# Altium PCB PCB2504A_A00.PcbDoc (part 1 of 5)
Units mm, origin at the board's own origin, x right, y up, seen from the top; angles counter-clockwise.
Board outline 115 x 60 mm, 6 copper layers (Top Layer, Signal Layer 2, Signal Layer 3, Signal Layer 4, Signal Layer 5, Bottom Layer), stack 1.555 mm thick; 403 components, 294 nets, 1344 pads, 774 vias.
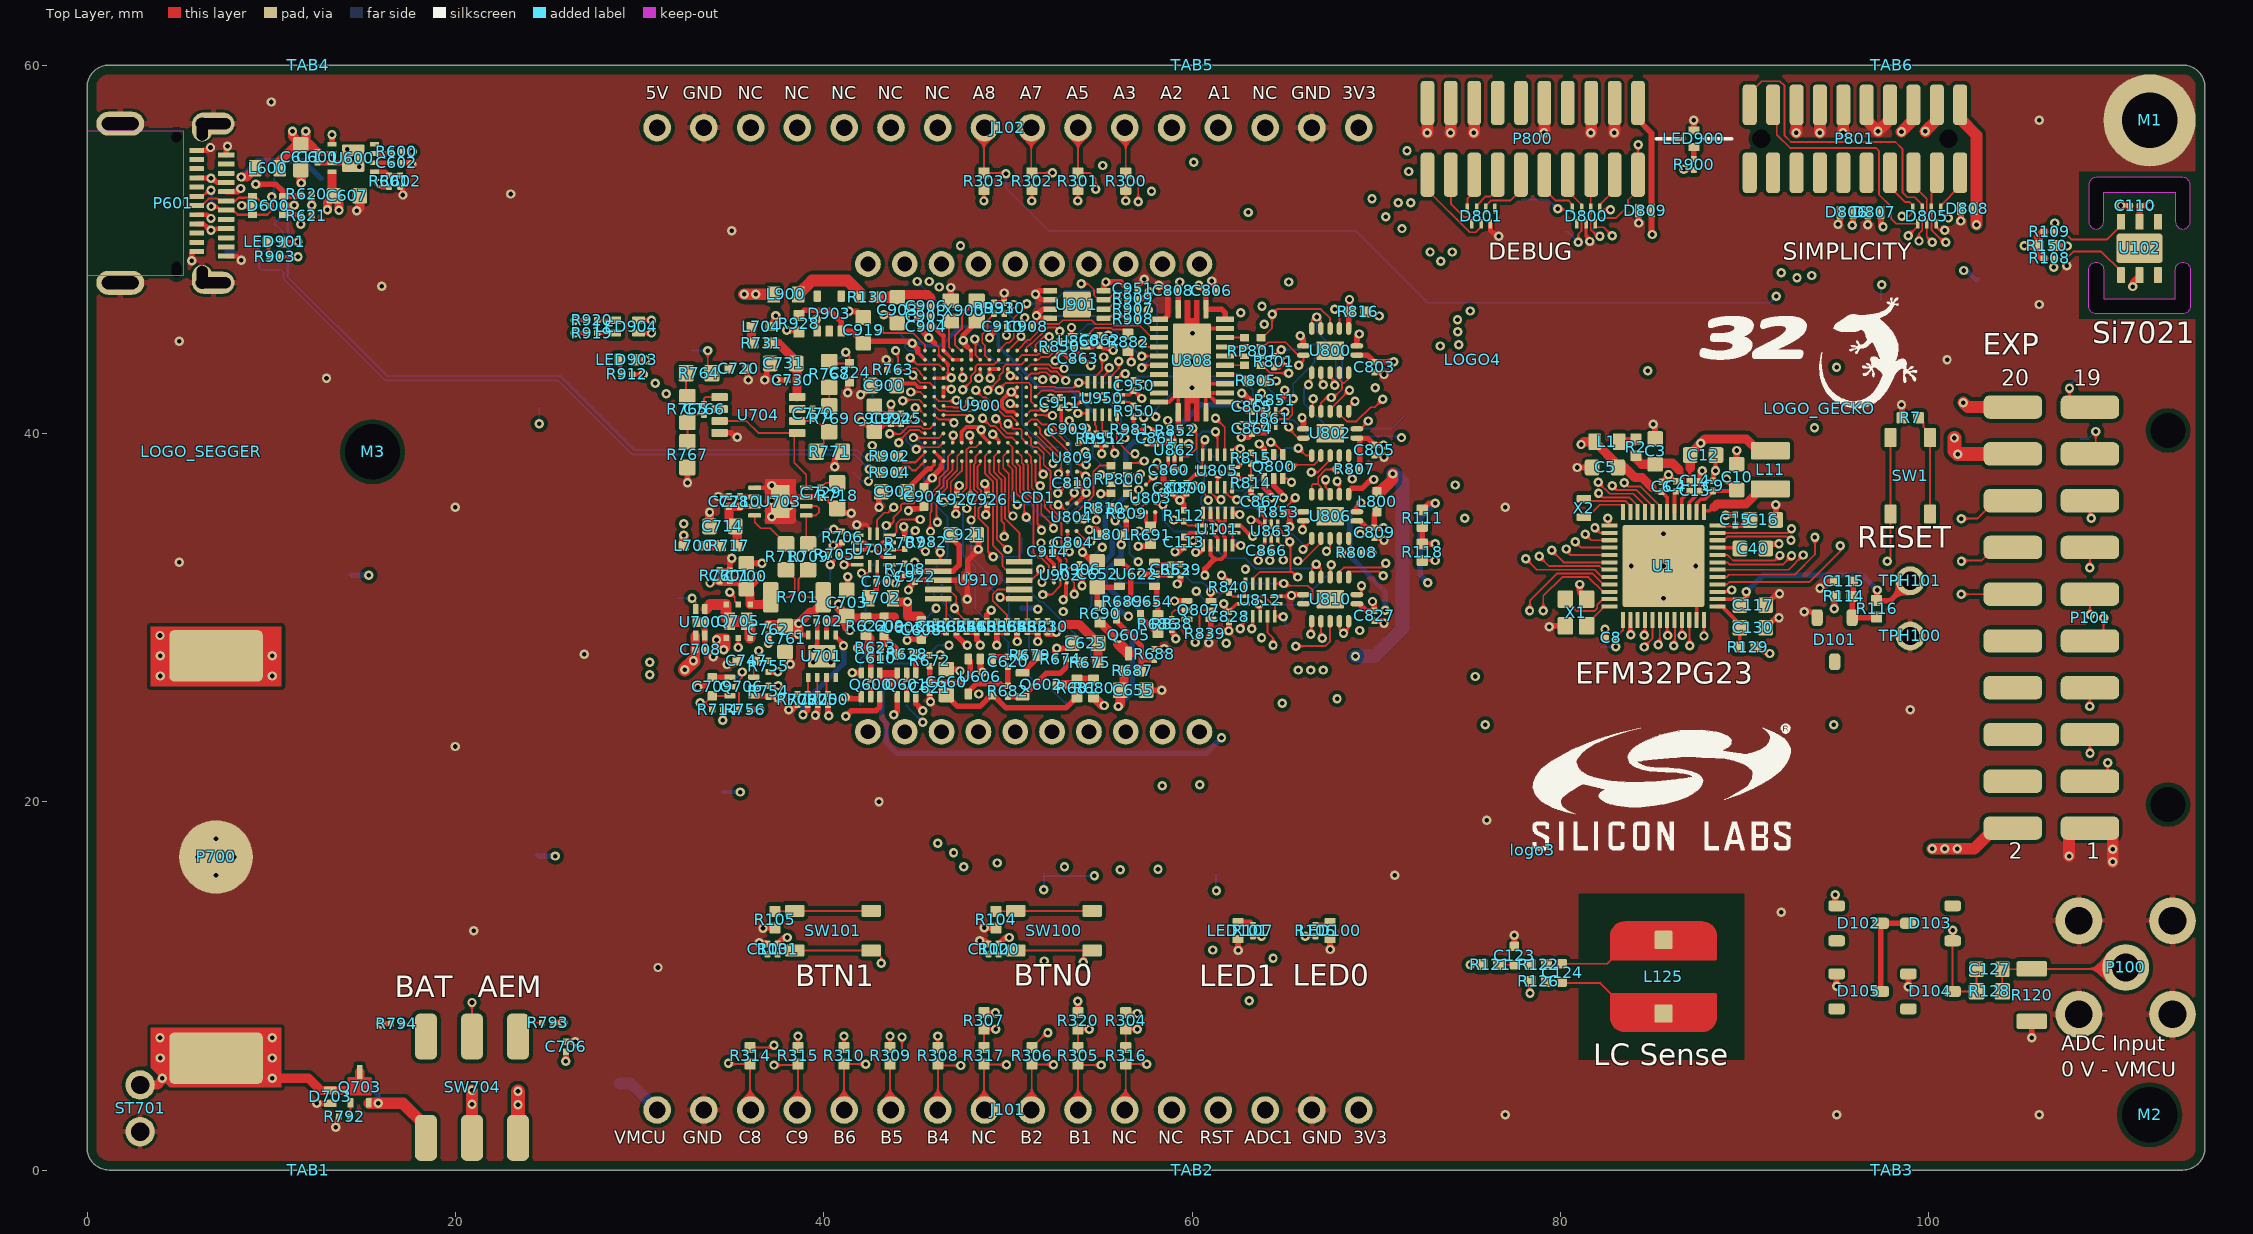
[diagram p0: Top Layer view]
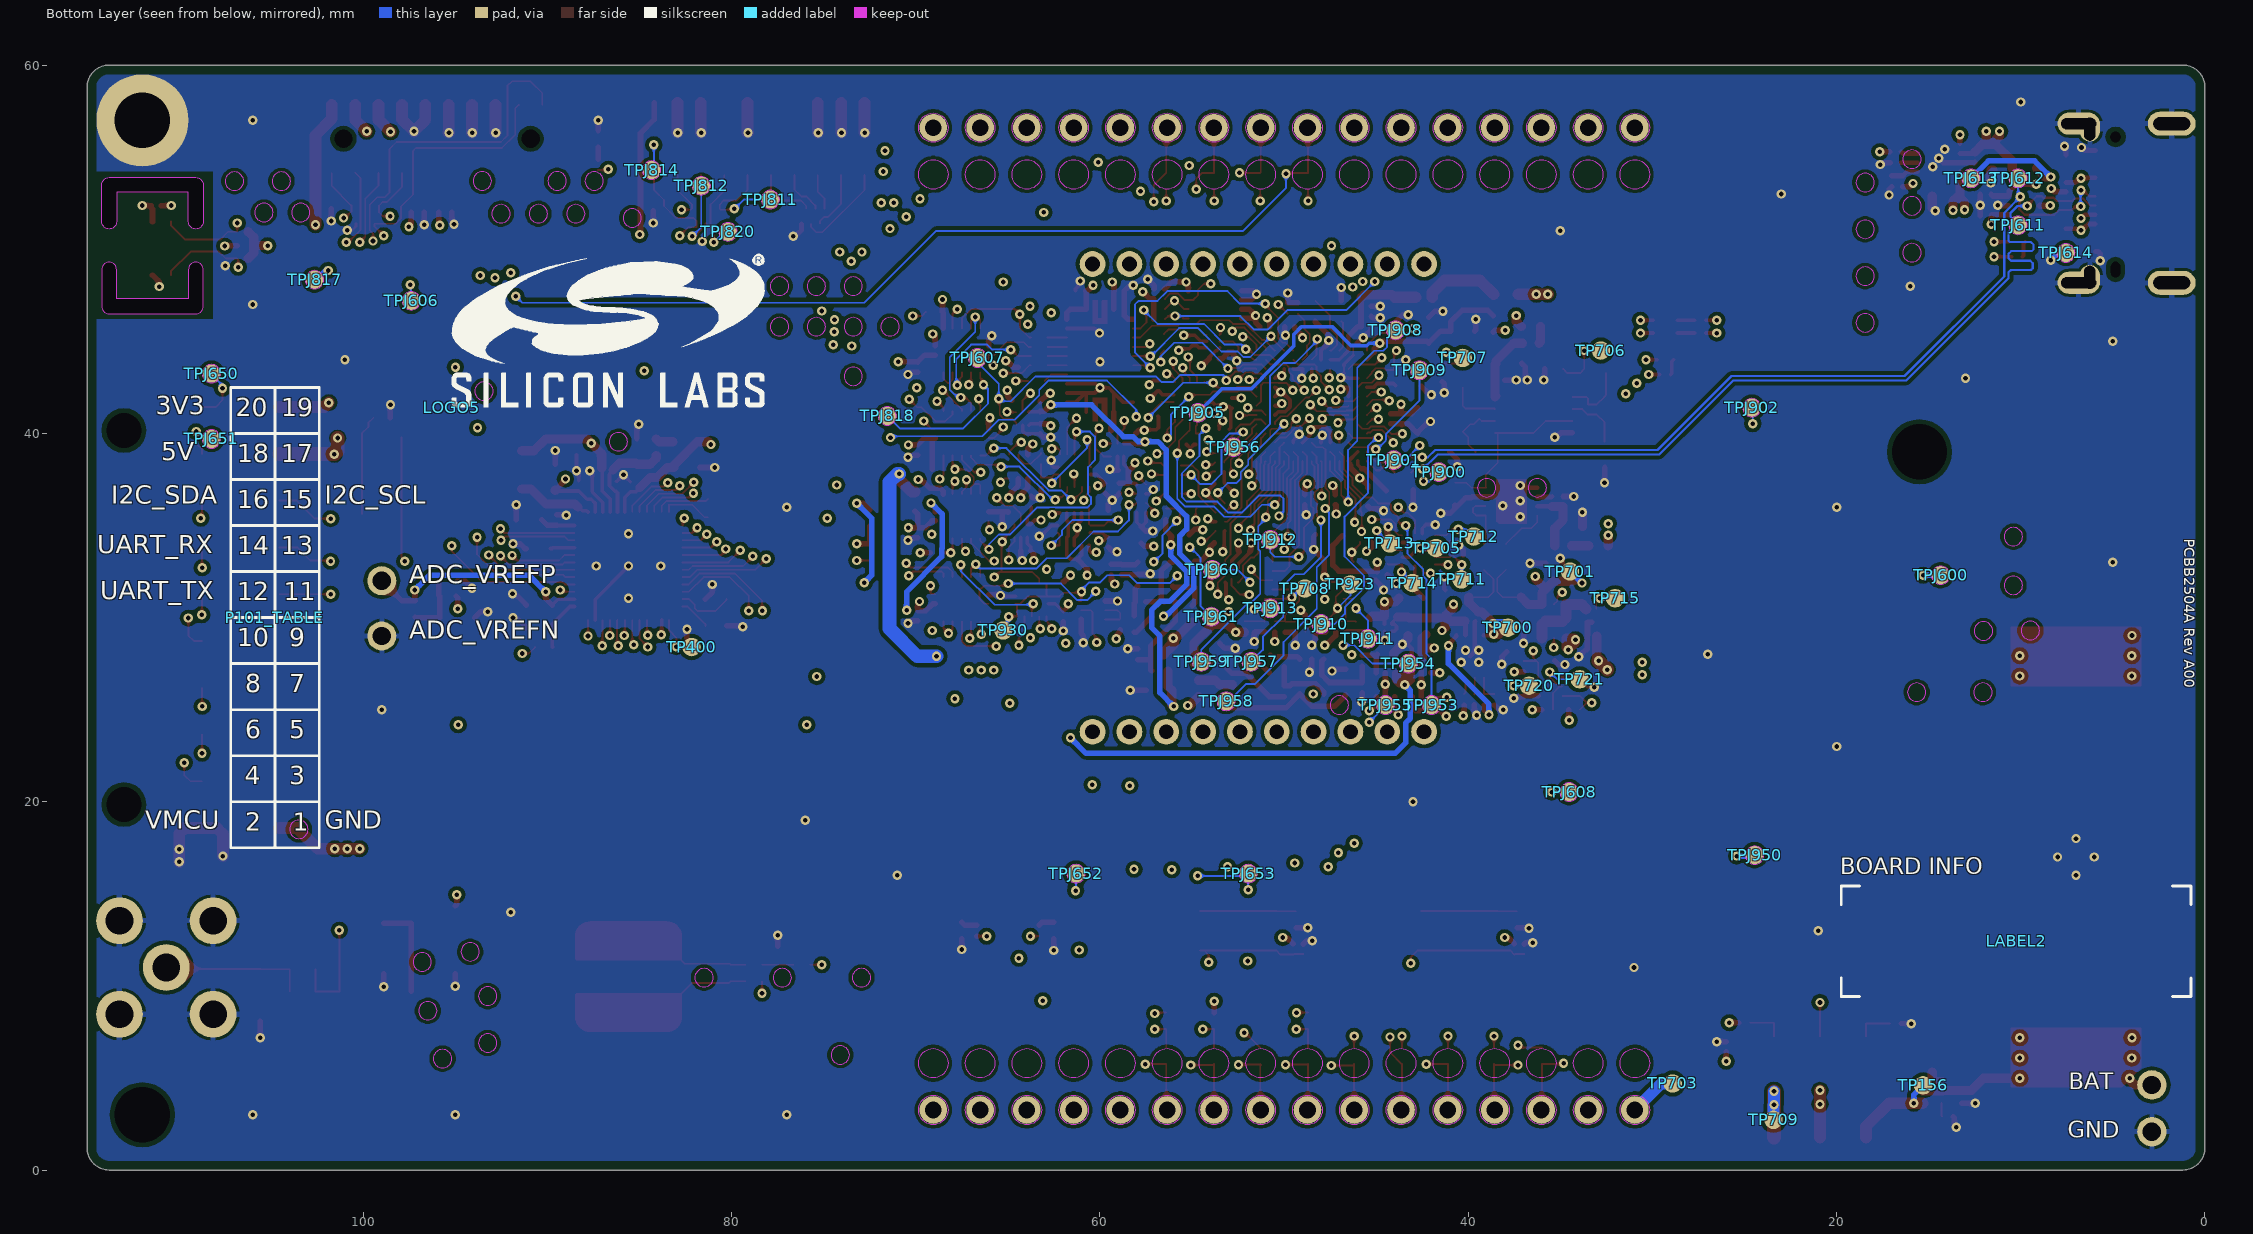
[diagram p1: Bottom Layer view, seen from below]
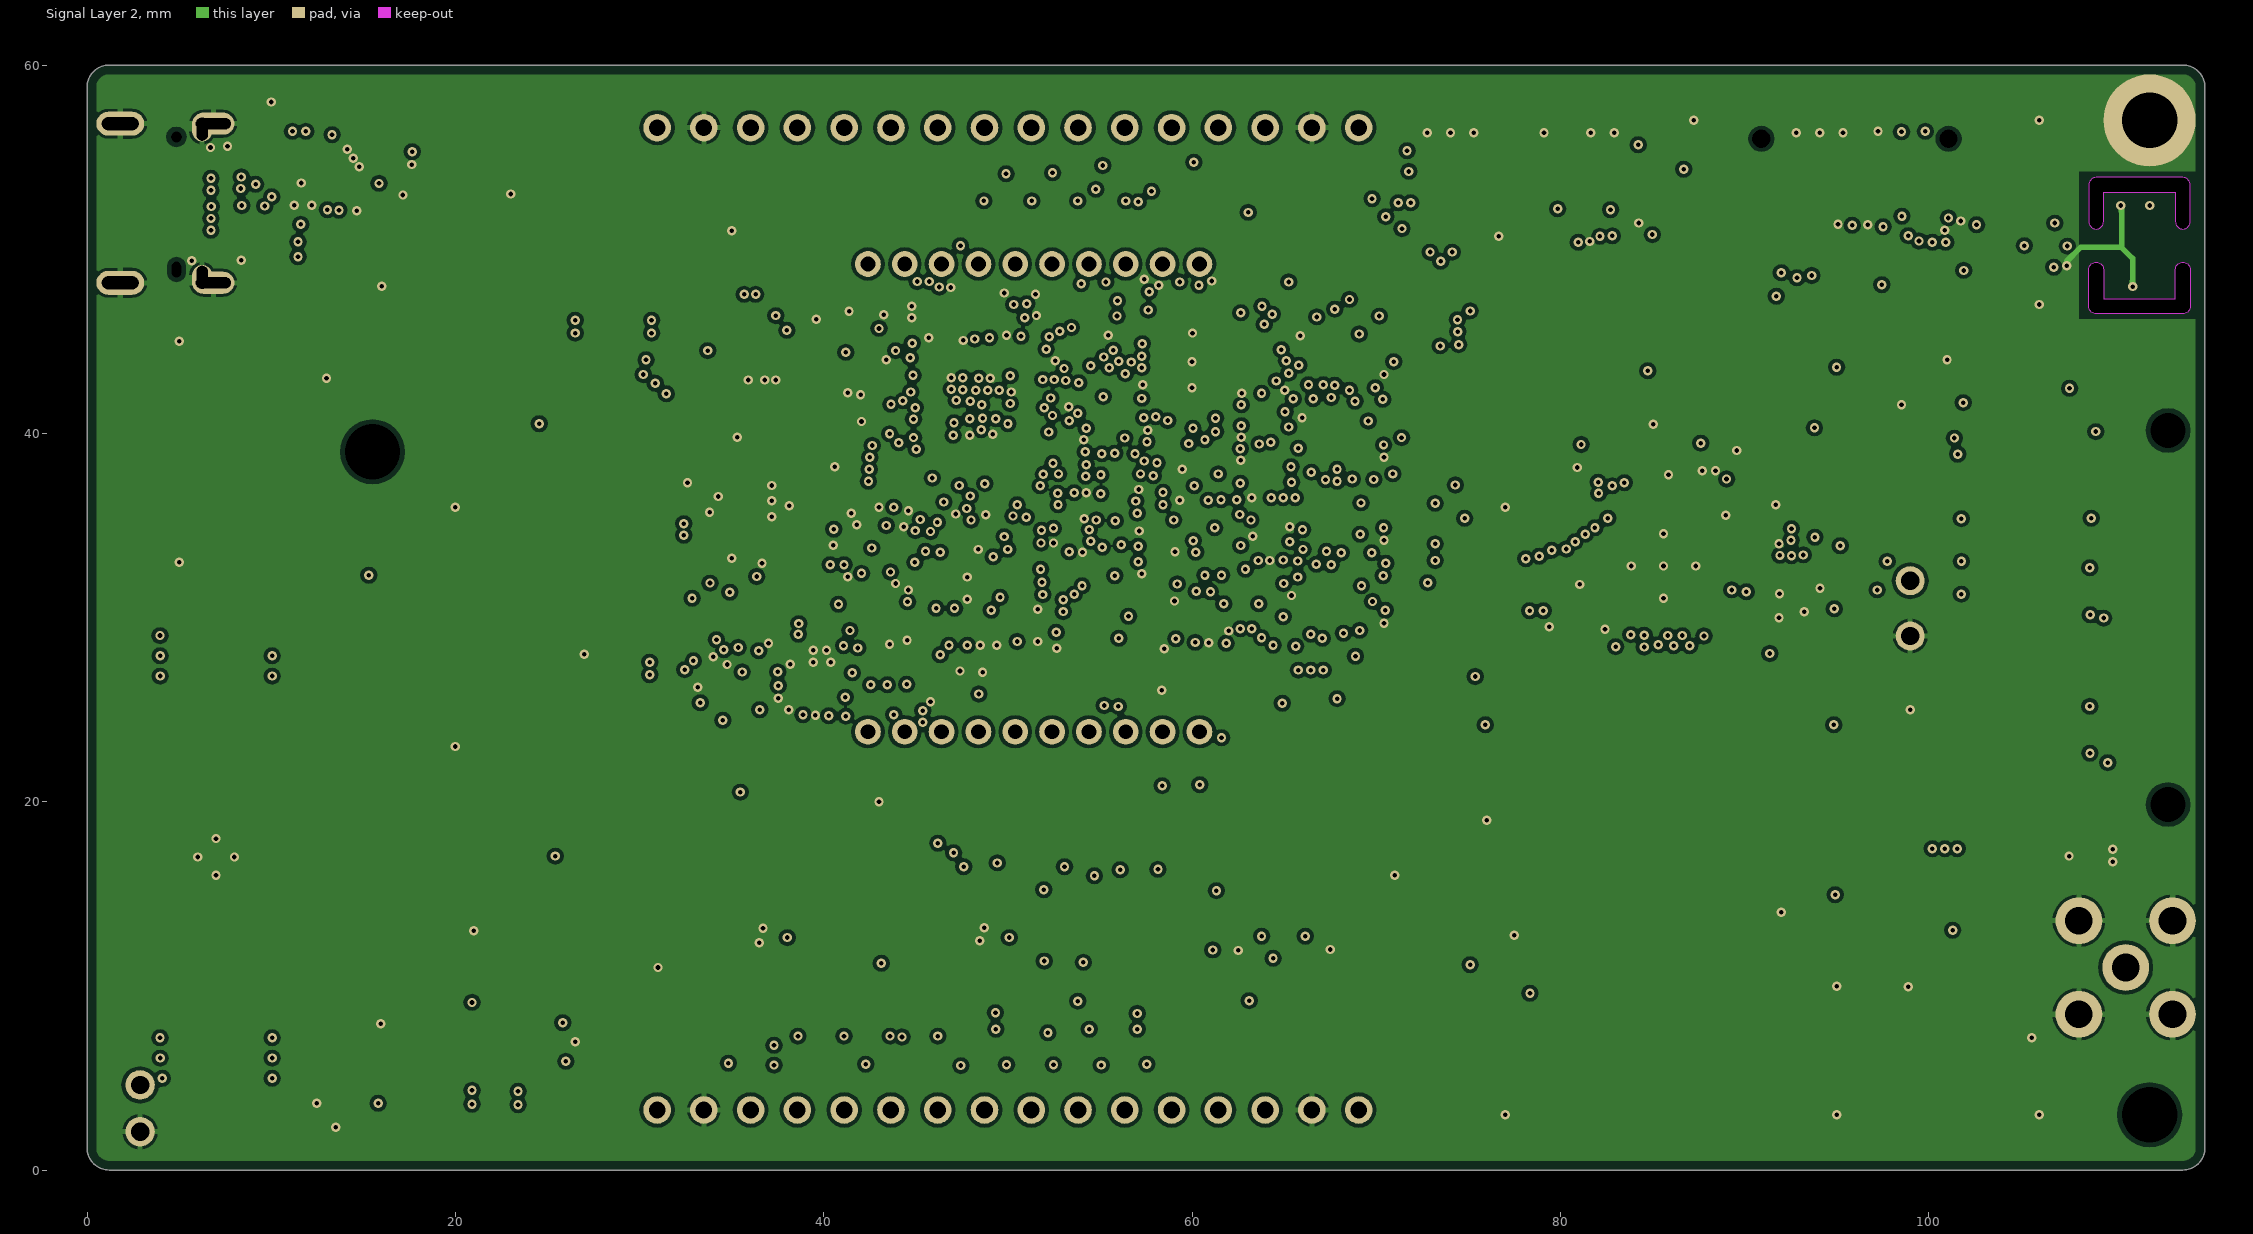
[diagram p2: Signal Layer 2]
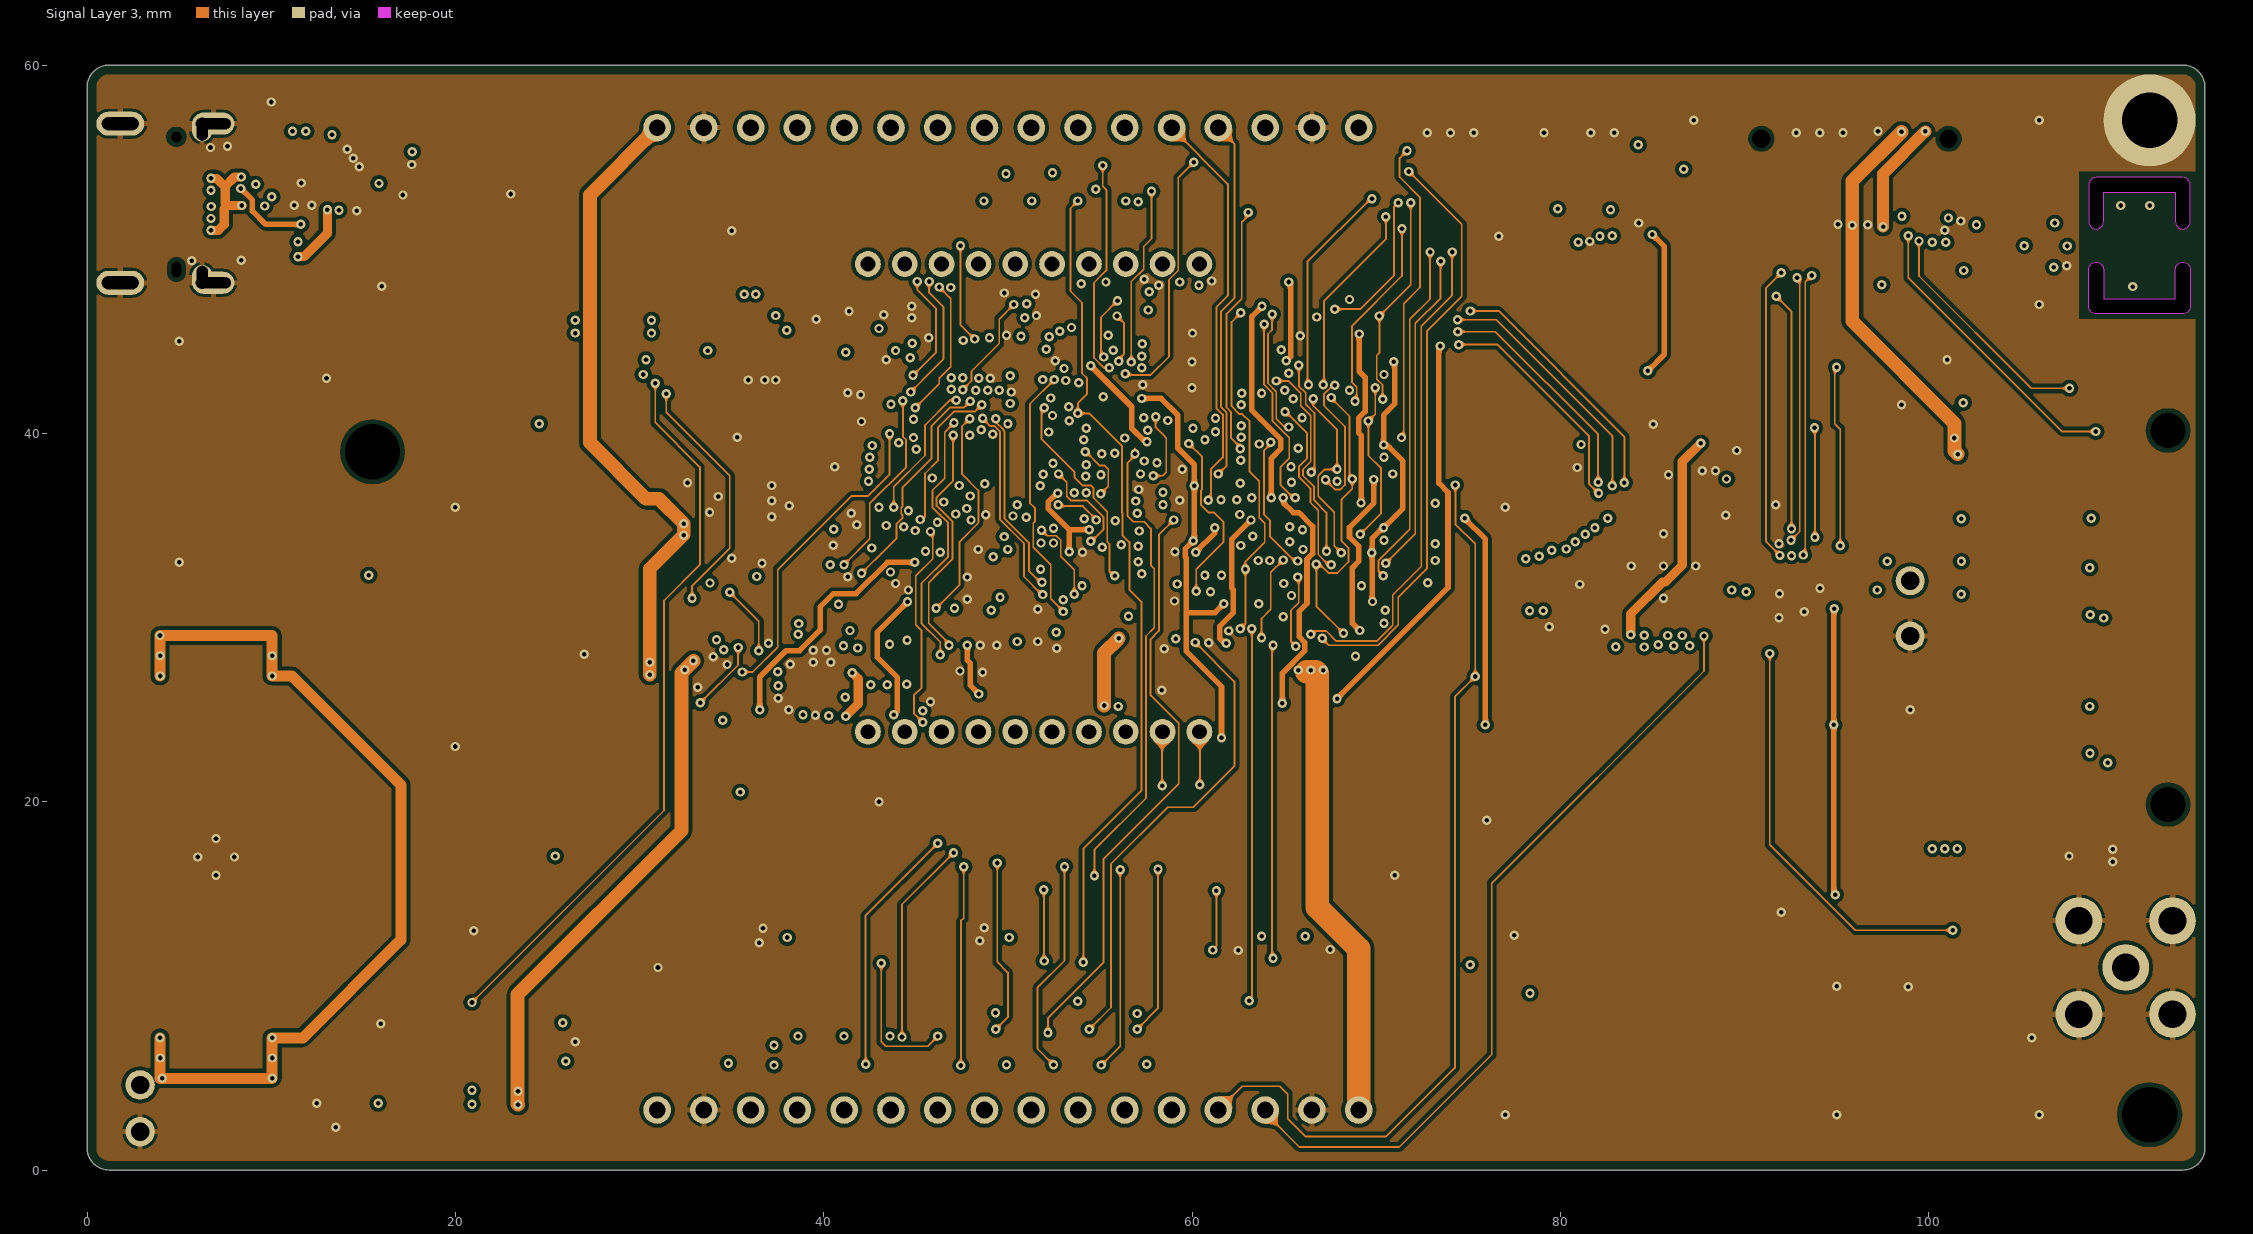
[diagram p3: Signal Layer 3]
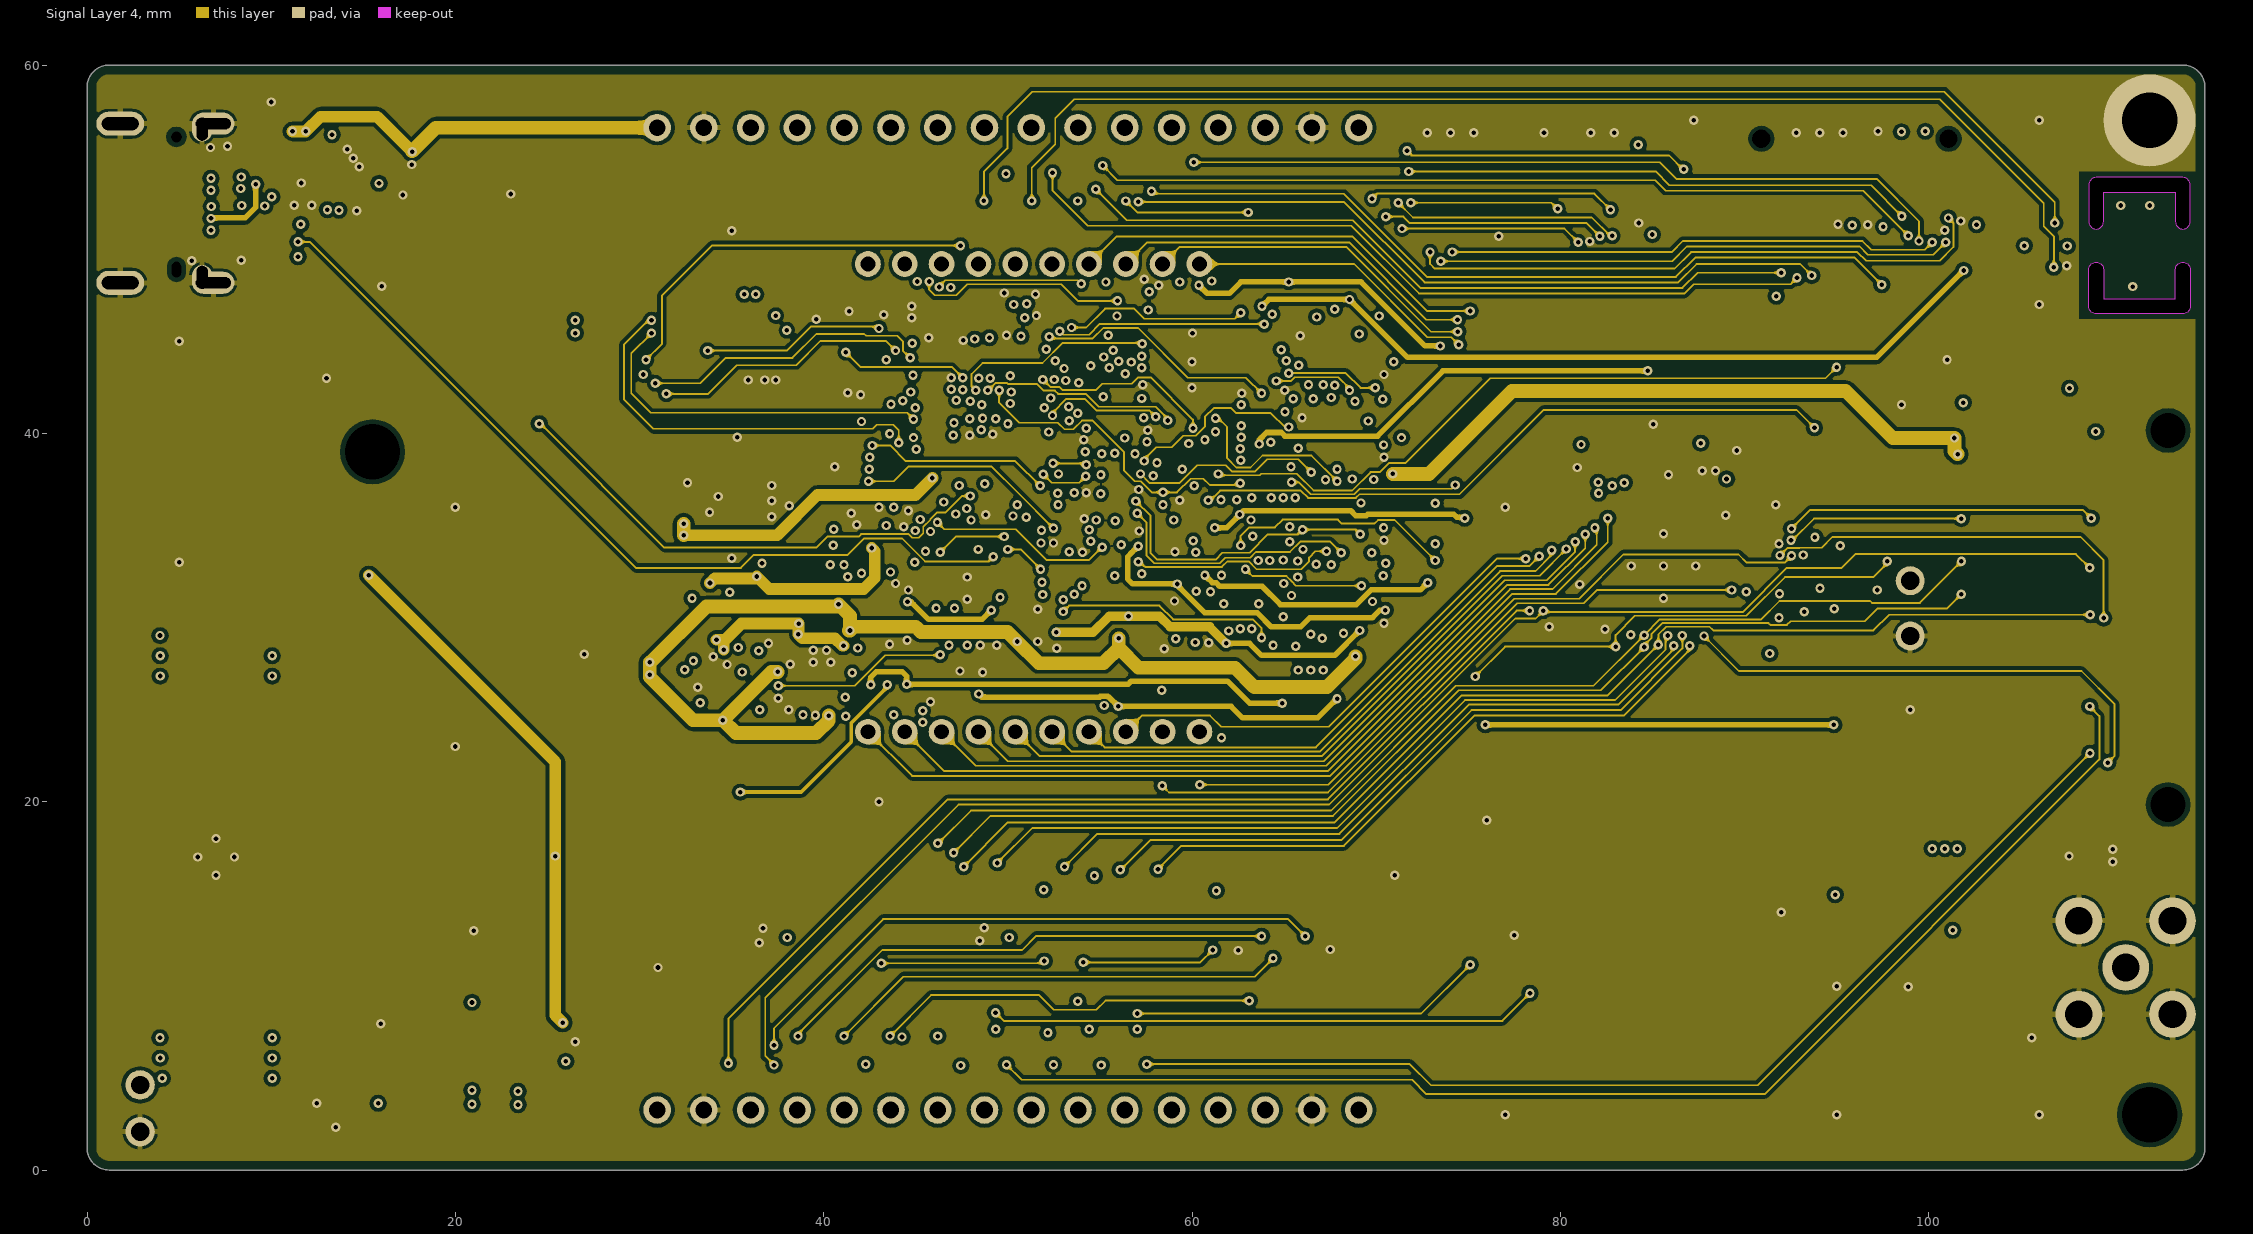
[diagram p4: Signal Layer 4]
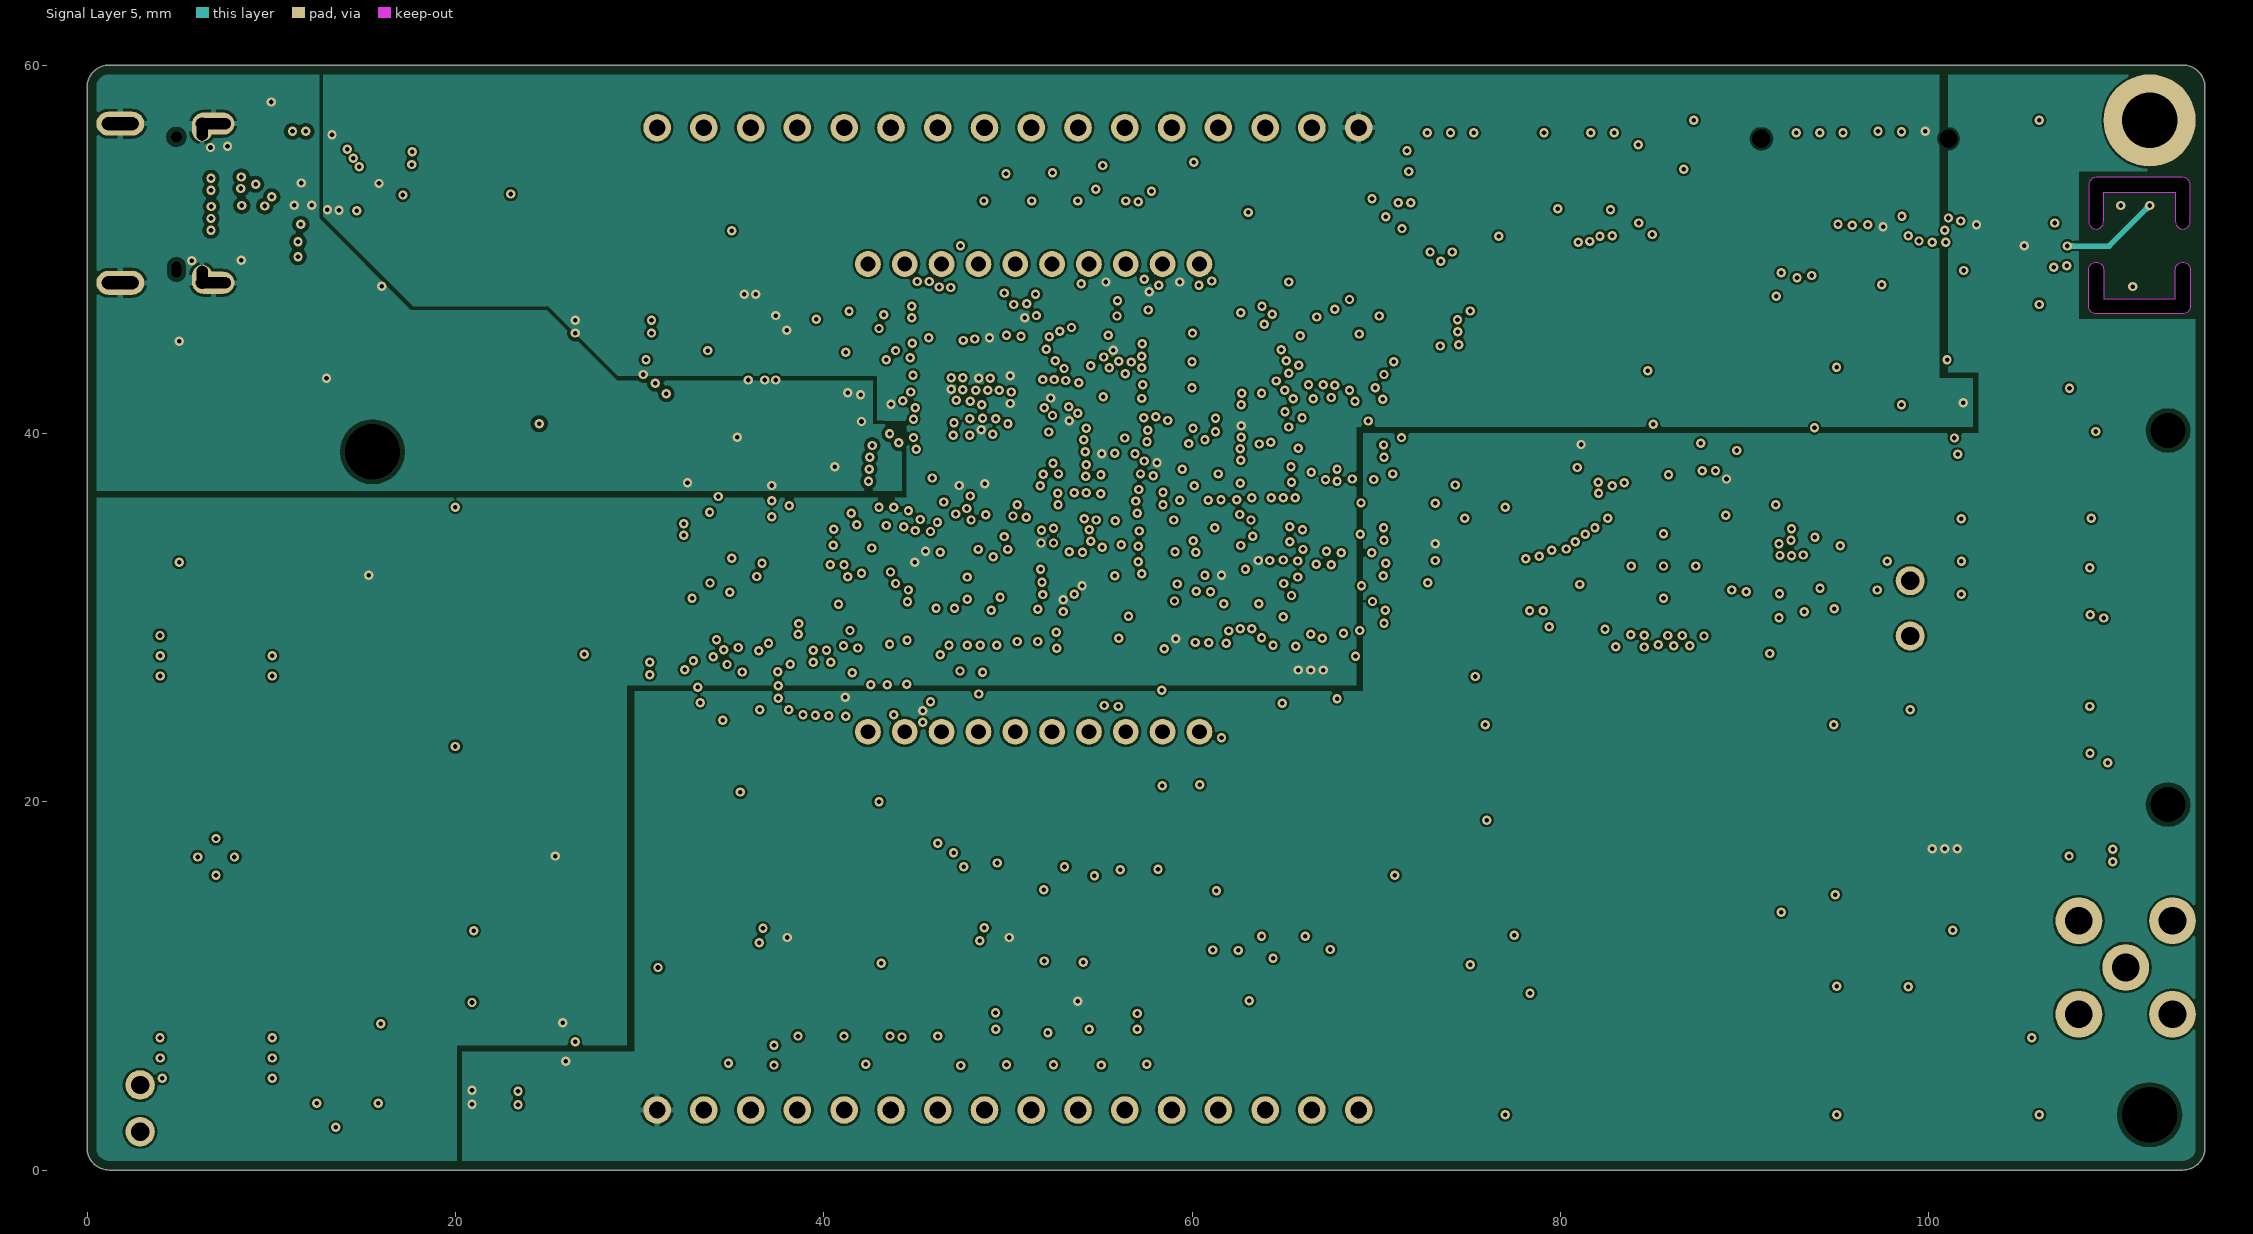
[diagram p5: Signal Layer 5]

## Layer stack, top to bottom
Top Solder: solder mask 0.03, Solder Resist, Dk 3.5
Top Layer: signal copper 0.035
Dielectric 1: prepreg 0.1, FR-4, Dk 4.2
Signal Layer 2: signal copper 0.035
Dielectric 2: core 0.46, Core-009, Dk 4.2
Signal Layer 3: signal copper 0.035
Dielectric 3: prepreg 0.225, PP-006, Dk 4.2
Signal Layer 4: signal copper 0.035
Dielectric 4: core 0.46, Core-009, Dk 4.2
Signal Layer 5: signal copper 0.035
Dielectric  5: prepreg 0.1, FR-4, Dk 4.2
Bottom Layer: signal copper 0.035
Bottom Solder: solder mask 0.03, Solder Resist, Dk 3.5

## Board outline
0,1.2 0,58.8 cw(c1.2,58.8) 1.2,60 113.8,60 cw(c113.8,58.8) 115,58.8 115,1.2 cw(c113.8,1.2) 113.8,0 1.2,0 cw(c1.2,1.2)
cut-out: 108.7,53.5 108.7,51.5 ccw(c109.1,51.5) 109.1,51.1 ccw(c109.1,51.5) 109.5,51.5 109.5,53.1 113.4,53.1 113.4,51.5 ccw(c113.8,51.5) 113.8,51.1 ccw(c113.8,51.5) 114.2,51.5 114.2,53.5 ccw(c113.8,53.5) 113.8,53.9 109.1,53.9 ccw(c109.1,53.5)
cut-out: 108.7,46.9 108.7,48.9 cw(c109.1,48.9) 109.1,49.3 cw(c109.1,48.9) 109.5,48.9 109.5,47.3 113.4,47.3 113.4,48.9 cw(c113.8,48.9) 113.8,49.3 cw(c113.8,48.9) 114.2,48.9 114.2,46.9 cw(c113.8,46.9) 113.8,46.5 109.1,46.5 cw(c109.1,46.9)

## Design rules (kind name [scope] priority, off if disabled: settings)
BoardOutlineClearance BoardOutlineClearance_IGNORE_USB [HasFootprint('FCI_10137065_USB-C_RCPT') and IsKeepOut] p1: gap=0.5 ignorepadtopadclearanceinfootprint=FALSE except(0: Region-OutlineEdge Region-CavityEdge Region-CutoutEdge Region-SplitBarrior Region-SplitContinuation; 0.26: Arc-CutoutEdge Track-CutoutEdge SMDPad-CutoutEdge THPad-CutoutEdge Via-CutoutEdge Fill-CutoutEdge Poly-CutoutEdge Text-CutoutEdge; 0.4: THPad-OutlineEdge)
BoardOutlineClearance [Not HasFootprint('TAB50.5_T1.6_W2.4') or not HasFootprint('FCI_10137065_USB-C_RCPT')] p2: gap=0.5 ignorepadtopadclearanceinfootprint=FALSE except(0.26: Arc-CutoutEdge Track-CutoutEdge SMDPad-CutoutEdge THPad-CutoutEdge Via-CutoutEdge Fill-CutoutEdge Poly-CutoutEdge Region-CutoutEdge Text-CutoutEdge; 0.4: THPad-OutlineEdge)
Clearance Clearance_NPL [(ObjectKind = 'Pad') And (Layer = 'MultiLayer') And (PadIsPlated = 'False')] p1: gap=0.25 ignorepadtopadclearanceinfootprint=FALSE
Clearance Clearance_Polygon_GND [InNet('GND') and InPolygon] p2: gap=0.2 ignorepadtopadclearanceinfootprint=FALSE
Clearance Clearance_Polygon_General [InPolygon] p3: gap=0.125 ignorepadtopadclearanceinfootprint=FALSE
Clearance Clearance_Via_Track [IsVia vs IsTrack] p4: gap=0.089 ignorepadtopadclearanceinfootprint=FALSE except(0: Arc-Hole Track-Hole SMDPad-Hole THPad-Hole Via-Hole Fill-Hole Poly-Hole Region-Hole Text-Hole)
Clearance [All] p5: gap=0.1 ignorepadtopadclearanceinfootprint=FALSE
ComponentClearance ComponentClearance_IGNORE [HasFootprint('TESTJIGG_PCB4002_M14') OR HasFootprint('TAB50.5_T1.6_W2.4') OR HasFootprint('TP_6.0X6.0_MILLOUT_5.0X5.0_TH') Or InComponent('M1')] p1: gap=0 collisioncheckmode=3 verticalgap=0 showdistances=FALSE
ComponentClearance [All] p2: gap=0.2 collisioncheckmode=3 verticalgap=0.254 showdistances=FALSE
DiffPairsRouting DiffPairsRouting_90OHM [InDifferentialPair('USB_90') or InDifferentialPair('USB_90_U900')] p1: maxlimit=0.254 minlimit=0.12 mostfreqgap=0.254 toplayer_maxgap=0.12 toplayer_prefgap=0.12 toplayer_minwidth=0.12 toplayer_maxwidth=0.12 toplayer_prefwidth=0.12 bottomlayer_maxgap=0.12 bottomlayer_prefgap=0.12 bottomlayer_minwidth=0.12 bottomlayer_maxwidth=0.12 bottomlayer_prefwidth=0.12 impedanceprofiledriven=TRUE impedanceprofileid={B4300C99-598D-4438-91CE-854F904B181D} impedanceprofilevalue=90.000000 maxuncoupledlength=50
HoleSize [All] p1: absolutevalues=TRUE maxlimit=10 minlimit=0.1 maxpercent=80.000 minpercent=20.000
HoleToHoleClearance HoleToHoleClearance_general [Not InComponent('P601')] p1: gap=0.254 allowstackedmicrovias=TRUE
MatchedLengths [All] p1: tolerance=0.1 checknetsindiffpair=TRUE checkdiffpairvsdiffpair=FALSE checkxsignals=FALSE checkothers=FALSE
MinimumSolderMaskSliver MinimumSolderMaskSliver_IGNORE [InComponent('LOGO*') vs InComponent('LOGO*')] p1: minsoldermaskwidth=0
MinimumSolderMaskSliver [All] p2: minsoldermaskwidth=0.1
PolygonConnect PolygonConnect_Direct_Connect [InComponent('M1') or InComponent('J1') or InComponent('P700')] p1: connectstyle=Direct reliefconductorwidth=0.33 reliefentries=4 polygonreliefangle="90 Angle" airgapwidth=0.152
PolygonConnect PolygonConnect_general [All] p2: thpad.connectstyle=Relief thpad.reliefconductorwidth=0.3 thpad.reliefentries=4 thpad.polygonreliefangle="90 Angle" thpad.airgapwidth=0.15 smdpad.connectstyle=NoConnect smdpad.reliefconductorwidth=0.33 smdpad.reliefentries=4 smdpad.polygonreliefangle="90 Angle" smdpad.airgapwidth=0.15 via.connectstyle=Direct via.reliefconductorwidth=0.33 via.reliefentries=4 via.polygonreliefangle="90 Angle" via.airgapwidth=0.127
RoutingVias RoutingVias_Through [InDrillLayerPair('Top Layer - Bottom Layer')] p1: holewidth=0.25 width=0.508 viastyle="Through Hole" minholewidth=0.25 minwidth=0.508 maxholewidth=1 maxwidth=1.5 useviatemplates=TRUE viatemplateguid#1={08D43F0E-9906-4177-A4FE-1C96C0EB29F0} viatemplatename#1=v51h25m0mx0(1)
ShortCircuit ShortCircuit_General [All] p1: allowed=FALSE
SilkToSilkClearance [All] p1: silktosilkclearance=0.102
SilkToSolderMaskClearance [IsPad] p1: minsilkscreentomaskgap=0.102 clearancetoexposedcopper=TRUE
SolderMaskExpansion [All] p1: expansion=0.05 istentingtop=FALSE
UnRoutedNet [All] p1: checkbadconnections=TRUE
Width [All] p1: maxlimit=5.08 minlimit=0.1 preferedwidth=0.1 minimp=50.000000 maximp=50.000000 favimp=50.000000
21 further rules are at their usual default settings.

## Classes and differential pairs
net class USB_90: N16942491 N16942503 USB_DM USB_DP
differential pair USB_90_U900: +N16942503 -N16942491
differential pair USB_90: +USB_DP -USB_DM
differential pair ETH_RX: +"" -""
differential pair ETH_TX: +"" -""
differential pair USB: +"" -""

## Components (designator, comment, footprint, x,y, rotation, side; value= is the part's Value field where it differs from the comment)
C3 "4U7" C0603 85.15,39.025 r90 top
C4 "10N" C0201 86.275,37.125 r90 top
C5 "4U7" C0603 82.425,38.15 r180 top
C6 "100N" C0201 85.5,37.1 r90 top
C8 "100N" C0201 82.725,28.9 r180 top
C9 "100N" C0201 88.3,37.15 r90 top
C10 "10U" C0603 89.575,37.625 r90 top
C12 "4U7" C0603 87.75,38.825 r0 top
C13 "100N" C0201 87.3,36.875 r0 top
C14 "100N" C0201 87.3,37.425 r0 top
C15 "100N" C0201 89.5,35.3 r90 top
C16 "1U" C0603 91,35.3 r0 top
C40 "4U7" C0603 90.45,33.75 r0 top
C102 "1N" C0201 48.95,12 r90 top
C103 "1N" C0201 36.95,12 r90 top
C110 "100N" C0201 111.2,52.35 r180 top
C113 "100N" C0201 59.55,34.1 r270 top
C115 "1U" C0402 95.4,31.975 r180 top
C117 "10U" C0603 90.45,30.675 r0 top
C123 "100N" C0402 77.5,11.65 r90 top
C124 "330P" C0402 80.1,10.7 r270 top
C127 "4U7" C0603 103.3,10.9 r180 top
C130 "10N" C0603 90.45,29.45 r0 top
C600 "100N" C0201 12.5,55 r270 top
C602 "33N" C0201 16.8,54.7 r0 top
C607 "10U" C0603 14.1,52.9 r0 top
C608 "1U" C0402 45.3,29.325 r270 top
C609 "1U" C0402 43.275,29.525 r270 top
C610 "1N" C0201 42.8,27.8 r0 top
C611 "10U" C0603 11.6,55 r270 top
C620 "100P" C0201 50,27.6 r90 top
C621 "100N" C0201 45.75,26.2 r270 top
C625 "10U" C0603 54.2,28.6 r180 top
C632 "10N" C0201 51.05,29.5 r270 top
C635 "10N" C0201 49.4,29.5 r270 top
C638 "10N" C0201 46.1,29.5 r270 top
C641 "10N" C0201 47.75,29.5 r270 top
C652 "10U" C0603 54.85,32.35 r90 top
C653 "100N" C0201 58.825,32.6 r270 top
C654 "100P" C0201 57.8,30.85 r0 top
C655 "10U" C0603 56.8,26.05 r0 top
C660 "10U" C0603 46.65,26.5 r90 top
C700 "10U" C0603 35.8,32.25 r90 top
C701 "100N" C0201 34.9,32.275 r90 top
C702 "100N" C0201 39.9,29.8 r180 top
C703 "10U" C0603 41.25,30.8 r90 top
C705 "33N" C0201 39.675,25.55 r270 top
C706 "100N" C0201 26,6.7 r90 top
C707 "100N" C0201 43.15,31.95 r0 top
C708 "100N" C0201 33.3,28.25 r0 top
C709 "100P" C0402 33.95,26.25 r90 top
C710 "100N" C0201 35.45,36.3 r90 top
C714 "10U" C0603 34.5,34.95 r180 top
C720 "1N" C0402 35.35,43.5 r0 top
C724 "1N" C0402 41.4,43.3 r270 top
C728 "100N" C0201 34.85,36.3 r90 top
C729 "2N2" C0201 39.825,36.775 r270 top
C730 "100N" C0201 38.3,42.9 r180 top
C731 "10U" C0603 37.8,43.8 r180 top
C747 "100P" C0402 35.8,27.65 r180 top
C761 "10U" C0603 37.9,28.85 r270 top
C762 "100N" C0201 37,29.35 r270 top
C766 "10P" C0201 33.5,41.3 r90 top
C770 "10P" C0201 39.4,41.075 r90 top
C800 "100N" C0201 59.7,37.025 r270 top
C803 "100N" C0201 69.9,43.6 r270 top
C804 "100N" C0201 53.525,34.05 r0 top
C805 "100N" C0201 69.9,39.1 r270 top
C806 "100N" C0201 61.05,47.75 r0 top
C807 "100N" C0201 58.95,37.025 r270 top
C808 "100N" C0201 58.95,47.75 r180 top
C809 "100N" C0201 69.9,34.6 r270 top
C810 "100N" C0201 53.5,37.3 r0 top
C827 "100N" C0201 69.9,30.1 r270 top
C828 "100N" C0201 62,30.05 r270 top
C860 "100N" C0201 58.725,38 r0 top
C861 "100N" C0201 58.05,39.725 r90 top
C862 "100N" C0201 54.975,45.05 r90 top
C863 "100N" C0201 53.8,44.05 r180 top
C864 "100N" C0201 63.25,40.25 r270 top
C865 "100N" C0201 63.25,41.45 r90 top
C866 "100N" C0201 64.025,33.625 r0 top
C867 "100N" C0201 63.725,36.3 r90 top
C900 "1U" C0603 43.25,42.6 r180 top
C901 "1U" C0402 45.45,36.55 r270 top
C902 "4U7" C0603 43.825,36.825 r180 top
C903 "10U" C0603 44,46.7 r270 top
C904 "10N" C0201 45.55,45.8 r180 top
C905 "10N" C0201 45.55,46.35 r180 top
C906 "10N" C0201 45.55,46.9 r180 top
C907 "4U7" C0603 42.75,40.8 r270 top
C908 "100N" C0201 51.05,45.8 r0 top
C909 "100N" C0201 53.25,40.225 r180 top
C910 "100N" C0201 49.7,45.8 r0 top
C911 "100N" C0201 52.825,41.675 r270 top
C914 "100N" C0201 52.15,33.575 r0 top
C919 "10U" C0603 42.15,45.6 r90 top
C921 "4U7" C0603 47.6,34.5 r0 top
C922 "100N" C0201 44.95,32.225 r270 top
C924 "100N" C0201 43.65,40.8 r270 top
C925 "100N" C0201 44.2,40.8 r270 top
C926 "100N" C0201 48.875,36.4 r270 top
C927 "100N" C0201 47.225,36.4 r270 top
C950 "10N" C0201 56.825,42.6 r90 top
C951 "100N" C0201 56.775,47.85 r0 top
D101 "ADR1581" SOT23_123 94.9,28.8 r270 top
D102 "BAT54" SOT23_123 96.2,13.4 r0 top
D103 "BAT54" SOT23_123 100.1,13.4 r180 top
D104 "BAT54" SOT23_123 100.1,9.7 r0 top
D105 "BZX84-C4V3" SOT23_123 96.2,9.7 r0 top
D600 "DT1446-04" SOT563_DIODES 9.825,52.375 r180 top
D703 "ESD" X2-DFN1006-2 13.2,3.975 r270 top
D800 "PUSB3AB6" DFN2111-7_M050_1.2X2.1_NXP 81.4,51.8 r270 top
D801 "PUSB3AB6" DFN2111-7_M050_1.2X2.1_NXP 75.7,51.8 r270 top
D805 "PUSB3AB6" DFN2111-7_M050_1.2X2.1_NXP 99.9,51.8 r270 top
D806 "ESD" X2-DFN1006-2 95.55,52 r180 top
D807 "ESD" X2-DFN1006-2 97.05,52 r180 top
D808 "ESD" X2-DFN1006-2 102.1,52.209 r180 top
D809 "ESD" X2-DFN1006-2 84.6,52.1 r180 top
D903 "LM4040C30IDCK" SC70-5 40.3,46.5 r90 top
J101 "1X16_2.54MM" HDR_M254-1X16_NO_3D 30.95,3.262 r0 top locked
J102 "1X16_2.54MM" HDR_M254-1X16_NO_3D 30.95,56.602 r0 top locked
L1 "74279266" COIL_WURTH_CBF_0603 82.525,39.55 r0 top
L11 "2U2" COIL_1008 91.4,38.025 r90 top
L125 "470uH" COIL_BOURNS_SDR0604 85.6,10.5 r270 top
L600 "742792662" COIL_WURTH_CBF_0603 9.8,54.4 r0 top
L700 "742792796" COIL_0402 32.925,33.9 r0 top
L702 "74279266" COIL_WURTH_CBF_0603 43.1,31.05 r180 top
L704 "742792796" COIL_0402 36.6,45.8 r180 top
L800 "742792796" COIL_0402 70.05,36.3 r270 top
L801 "742792796" COIL_0402 55.675,34.5 r180 top
L900 "74279266" COIL_WURTH_CBF_0603 37.95,47.55 r0 top
LABEL2 "Comment" LABEL_4CORNERS_19.0X6.0 10.25,12.425 r180 bottom
LCD1 "CE322-1002-01" LCD_TRI-T_CE322-1002-01 51.4,36.5 r0 top locked
LED100 "Yellow" LED_0402_CAT2 67.5,13 r270 top locked
LED101 "Yellow" LED_0402_CAT2 62.5,13 r270 top locked
LED900 "YELLOW" LED_0402_CAT2 87.25,56 r90 top
LED901 "BLUE" LED_0402_CAT2 10.2,50.4 r0 top
LED903 "RED" LED_0402 29.3,44 r180 top
LED904 "LED_G_R" LED_AVAGO_HSMF-C165-4 29.3,45.8 r0 top
logo3 "Comment" LOGO_SILABS_W14.0_SILK 78.5,17.4 r0 top locked
LOGO4 "Comment" LOGO_EFM32_W18.0 75.232,44 r0 top locked
LOGO5 "Comment" LOGO_SILABS_W18.0 95.2,41.4 r180 bottom locked
LOGO_GECKO "Comment" LOGO_GECKO_H6.0 94.05,41.35 r0 top locked
LOGO_SEGGER "Comment" LOGO_SEGGER_10.0X5.0_SM 6.2,39 r0 top locked
M1 "HOLE_PTH_3MM" HOLE_3.0_5.0_PL 112,57 r0 top locked
M2 "Comment" HOLE_3.0_NPL 112,3 r0 top locked
M3 "Comment" HOLE_3.0_NPL 15.5,39 r90 top locked
P100 "SMA" WELLSHOW_C02AN31_SMA_TH 110.7,11 r0 top
P101 "HEADER_2X10_2.54MM_TH" WCON_1125B-1210_HOR_PEG-2X10 113,19.84 r90 top locked
P101_TABLE "Comment" LABEL_P101_PIN_TABLE_SL 104.8,30 r180 bottom
P601 "AMPH_10137065" FCI_10137065_USB-C_RCPT 4.85,52.5 r270 top
P700 "CR2032" BAT_HOLD_MPD_BK-912_CR2032 7,17 r270 top locked
P800 "HEADER_DEBUG_ETM" WCON_3132_HDR_M127_SMD-2X10 78.5,56 r180 top locked
P801 "HEADER_2X10_1.27MM_SMD" HDR_SULLINS_M127_PEG-2X10 101.08,56 r180 top locked
Q600 "BSS84" SOT563 42.55,26.35 r90 top
Q601 "DMN5L06VK" SOT563 44.5,26.35 r90 top
Q602 "BC846BWT1G" SC70_123 51.8,26.35 r0 top
Q605 "BC846BWT1G" SC70_123 56.55,29.05 r270 top
Q703 "DMG3415" X2-DFN2015-3_DIODES 14.8,4.55 r90 top
Q705 "SiA975DJ" POWERPAK_SC70-6 35.35,29.8 r90 top
Q706 "DMN5L06VK" SOT563 35.55,26.25 r180 top
Q800 "DMN5L06VK" SOT563 64.425,38.2 r270 top
Q807 "DMN5L06VK" SOT563 60.375,30.4 r180 top
R2 "1R" R0402 84.1,39.25 r270 top
R7 "100R" R0402 99,40.85 r0 top
R100 "1M" R0201 49.5,12 r90 top
R101 "1M" R0201 37.5,12 r90 top
R104 "100R" R0402 49.35,13.6 r270 top
R105 "100R" R0402 37.35,13.6 r270 top
R106 "2K05" R0201 66.7,13 r270 top
R107 "2K05" R0201 63.3,13 r270 top
R108 "4K7" R0201 106.55,49.5 r0 top
R109 "4K7" R0201 106.55,50.95 r0 top
R111 "0R" R0402 72.5,35.4 r90 top
R112 "10M" R0201 59.55,35.525 r90 top
R114 "16K2" R0402 95.4,31.15 r180 top
R116 "205R" R0402 97.175,30.475 r270 top
R118 "10K" R0402 72.5,33.55 r270 top
R120 "49R9" R1206 105.6,9.5 r90 top
R121 "100R" R0402 76.2,11.15 r0 top
R122 "0R" R0402 78.8,11.15 r0 top
R126 "1K5" R0402 78.8,10.25 r0 top
R128 "549R" R0603 103.3,9.7 r180 top
R129 "14R" R0402 90.175,28.4 r180 top
R130 "1R" R0402 42.4,47.4 r0 top
R150 "0R" R0402 106.4,50.2 r180 top
R300 "0R" R0402 56.4,53.7 r270 top
R301 "0R" R0402 53.8,53.7 r270 top
R302 "0R" R0402 51.3,53.7 r270 top
R303 "0R" R0402 48.7,53.7 r270 top
R304 "0R" R0402 56.4,8.1 r90 top
R305 "1K" R0402 53.8,6.2 r90 top
R306 "0R" R0402 51.3,6.2 r90 top
R307 "0R" R0402 48.7,8.1 r90 top
R308 "0R" R0402 46.2,6.2 r90 top
R309 "0R" R0402 43.6,6.2 r90 top
R310 "0R" R0402 41.1,6.2 r90 top
R314 "0R" R0402 36,6.2 r90 top
R315 "0R" R0402 38.6,6.2 r90 top
R316 "0R" R0402 56.4,6.2 r270 top
R317 "0R" R0402 48.7,6.2 r270 top
R320 "10K" R0402 53.8,8.1 r90 top
R600 "10K" R0201 16.8,55.3 r0 top
R601 "180K" R0201 16.4,53.7 r270 top
R602 "110K" R0201 17,53.7 r90 top
R620 "5K1" R0201 11.9,52.975 r180 top
R621 "5K1" R0201 11.9,51.825 r180 top
R622 "47R" R0402 42.3,29.525 r90 top
R623 "10K" R0201 42.8,28.35 r180 top
R628 "1M" R0402 44.5,28 r180 top
R629 "1K" R0201 59.375,32.6 r270 top
R630 "4K7" R0201 52.15,29.5 r270 top
R631 "10K" R0201 51.6,29.5 r90 top
R633 "47K" R0201 50.5,29.5 r270 top
R634 "47K" R0201 49.95,29.5 r90 top
R636 "47K" R0201 47.2,29.5 r270 top
R637 "47K" R0201 46.65,29.5 r90 top
R639 "47K" R0201 48.85,29.5 r90 top
R640 "47K" R0201 48.3,29.5 r90 top
R672 "1K" R0201 45.75,27.65 r90 top
R674 "4K7" R0201 52.85,27.75 r180 top
R675 "3R3" R0402 54.45,27.55 r0 top
R679 "0R" R0402 51.2,27.95 r0 top
R680 "0R" R0402 54.65,26.15 r90 top
R681 "33R" R0402 53.75,26.15 r90 top
R682 "10K" R0201 50,26 r90 top
R686 "0R" R0402 58.15,29.65 r270 top
R687 "3R3" R0402 56.75,27.1 r180 top
R688 "4K7" R0201 57.95,28 r90 top
R689 "10K" R0201 56.2,30.85 r0 top
R690 "33R" R0402 55,30.2 r270 top
R691 "1M" R0402 57.75,34.475 r90 top
R700 "10K" R0201 40.225,25.55 r270 top
R701 "4R7" R1206 38.55,31.1 r180 top
R702 "180K" R0201 39.125,25.55 r270 top
R703 "110K" R0201 38.575,25.55 r90 top
R705 "1K" R0201 40.575,33.4 r0 top
R706 "15K" R0201 41,34.375 r90 top
R707 "33K" R0201 44.4,34.025 r270 top
R708 "1M" R0201 44.4,32.625 r90 top
R709 "1K8" R0603 39.15,33.3 r270 top
R710 "1K8" R0603 37.95,33.3 r270 top
R714 "10K" R0201 34.25,25 r0 top
R717 "10R" R0402 34.85,33.9 r0 top
R718 "12K" R0603 40.725,36.625 r90 top
R731 "1R" R0402 36.6,44.9 r180 top
R754 "100K" R0201 37,26 r90 top
R755 "10K" R0201 37,27.35 r270 top
R756 "100K" R0201 35.7,25 r0 top
R760 "330K" R0201 34.35,32.275 r270 top
R763 "100K" R0201 43.75,43.45 r0 top
R764 "90R9" R0603 33.225,43.275 r0 top
R765 "51K" R0603 32.6,41.3 r90 top
R767 "160R" R0603 32.6,38.85 r90 top
R768 "90R9" R0603 40.3,43.2 r90 top
R769 "51K" R0603 40.3,40.8 r90 top
R771 "51K" R0603 40.3,39 r180 top
R792 "1K" R0201 13.975,2.9 r0 top
R793 "10K" R0201 25,8 r0 top
R794 "510K" R0201 16.8,7.95 r180 top
R801 "47K" R0201 64.45,43.9 r270 top
R805 "33R" R0402 63.45,42.85 r0 top
R807 "4K7" R0201 68.8,38.05 r180 top
R808 "4K7" R0201 68.925,33.525 r180 top
R809 "100K" R0201 56.425,35.625 r270 top
R810 "33R" R0402 55.2,35.925 r0 top
R814 "100K" R0201 63.2,37.3 r90 top
R815 "1K" R0201 63.2,38.65 r270 top
R816 "100K" R0402 69,46.6 r180 top
R838 "100K" R0201 58.9,29.625 r270 top
R839 "10M" R0201 60.7,29.125 r180 top
R840 "100K" R0201 62,31.65 r90 top
R850 "100K" R0201 52.8,44.7 r90 top
R851 "100K" R0201 64.5,41.8 r180 top
R852 "100K" R0201 59.1,40.15 r180 top
R853 "100K" R0201 64.675,35.725 r180 top
R882 "220R" R0402 56.525,44.95 r270 top
R900 "2K05" R0201 87.25,54.6 r90 top
R902 "33R" R0402 43.55,38.75 r0 top
R903 "5K76" R0201 10.2,49.6 r180 top
R904 "33R" R0402 43.55,37.875 r0 top
R906 "10K" R0201 53.899,32.598 r270 top
R907 "4K7" R0201 56.775,46.75 r180 top
R908 "4K7" R0201 56.775,46.2 r180 top
R909 "10K" R0201 56.775,47.3 r180 top
R912 "2K15" R0201 29.3,43.2 r180 top
R919 "1K" R0201 27.4,45.45 r0 top
R920 "1K" R0201 27.4,46.15 r0 top
R928 "100R" R0402 38.65,45.95 r270 top
R930 "1K" R0201 49.8,46.8 r90 top
R931 "1K" R0201 49.25,46.8 r90 top
R950 "100K" R0201 56.825,41.2 r270 top
R951 "100K" R0201 54.8,39.7 r90 top
R952 "100K" R0201 55.3,39.7 r90 top
R981 "100K" R0201 56.65,40.2 r0 top
R982 "10K" R0201 45.575,34.1 r0 top
RP800 "33R" RES_MNR04-8 56.05,37.5 r90 top
RP801 "33R" RES_MNR04-8 63.3,44.45 r90 top
ST701 "2X1_2.54MM" HDR_M254-1X2 2.875,2.08 r90 top locked
SW1 "PTS810" SW_CK_PTS810_SJM_250 99,37.7 r90 top locked
SW100 "PTS810" SW_CK_PTS810_SJM_250 52.5,13 r0 top locked
SW101 "PTS810" SW_CK_PTS810_SJM_250 40.5,13 r0 top locked
SW704 "DPDT_SW_SMD" CK_DPDT_JS202011SCQN 20.9,4.5 r180 top locked
TAB1 "Comment" TAB_V-CUT_L7.0_W2.4 12,0 r180 top locked
TAB2 "Comment" TAB_V-CUT_L7.0_W2.4 60,0 r180 top locked
TAB3 "Comment" TAB_V-CUT_L7.0_W2.4 98,0 r180 top locked
TAB4 "Comment" TAB_V-CUT_L7.0_W2.4 12,60 r0 top locked
TAB5 "Comment" TAB_V-CUT_L7.0_W2.4 60,60 r0 top locked
TAB6 "Comment" TAB_V-CUT_L7.0_W2.4 98,60 r0 top locked
TP156 "TP_SMD" TP_1.0_SMD 15.3,4.6 r180 bottom
TP400 "TP_SMD" TP_1.0_SMD 82.175,28.4 r180 bottom
TP700 "TP_SMD" TP_1.0_SMD 37.85,29.45 r90 bottom
TP701 "TP_SMD" TP_1.0_SMD 34.475,32.5 r90 bottom
TP703 "TP_SMD" TP_1.0_SMD 28.9,4.7 r180 bottom
TP705 "TP_SMD" TP_1.0_SMD 41.75,33.775 r180 bottom
TP706 "TP_SMD" TP_1.0_SMD 32.8,44.5 r90 bottom
TP707 "TP_SMD" TP_1.0_SMD 40.3,44.1 r90 bottom
TP708 "TP_SMD" TP_1.0_SMD 48.875,31.575 r90 bottom
TP709 "TP_SMD" TP_1.0_SMD 23.425,2.725 r90 bottom
TP711 "TP_SMD" TP_1.0_SMD 40.375,32.075 r90 bottom
TP712 "TP_SMD" TP_1.0_SMD 39.7,34.4 r90 bottom
TP713 "TP_SMD" TP_1.0_SMD 44.255,34.025 r90 bottom
TP714 "TP_SMD" TP_1.0_SMD 43.025,31.875 r90 bottom
TP715 "TP_SMD" TP_1.0_SMD 32.025,31.05 r180 bottom
TP720 "TP_SMD" TP_1.0_SMD 36.7,26.3 r90 bottom
TP721 "TP_SMD" TP_1.0_SMD 33.95,26.65 r90 bottom
TP923 "TP_SMD" TP_1.0_SMD 46.4,31.8 r90 bottom
TP930 "TP_SMD" TP_1.0_SMD 65.25,29.3 r180 bottom
TPH100 "PROTO_TH" PROTO_TH 99,29 r0 top
TPH101 "PROTO_TH" PROTO_TH 99,32 r0 top
TPJ600 "TP_SMD" TP_1.0_SMD 14.353,32.302 r90 bottom locked
TPJ606 "TP_SMD" TP_1.0_SMD 97.404,47.202 r90 bottom locked
TPJ607 "TP_SMD" TP_1.0_SMD 66.653,44.101 r90 bottom locked
TPJ608 "TP_SMD" TP_1.0_SMD 34.528,20.527 r90 bottom locked
TPJ611 "TP_SMD" TP_1.0_SMD 10.15,51.3 r180 bottom locked
TPJ612 "TP_SMD" TP_1.0_SMD 10.15,53.85 r180 bottom locked
TPJ613 "TP_SMD" TP_1.0_SMD 12.7,53.85 r180 bottom locked
TPJ614 "TP_SMD" TP_1.0_SMD 7.55,49.8 r180 bottom locked
TPJ650 "TP_SMD" TP_1.0_SMD 108.25,43.248 r90 bottom locked
TPJ651 "TP_SMD" TP_1.0_SMD 108.25,39.7 r90 bottom locked
TPJ652 "TP_SMD" TP_1.0_SMD 61.303,16.102 r90 bottom locked
TPJ653 "TP_SMD" TP_1.0_SMD 51.953,16.102 r90 bottom locked
TPJ811 "TP_SMD" TP_1.0_SMD 77.9,52.7 r180 bottom locked
TPJ812 "TP_SMD" TP_1.0_SMD 81.65,53.45 r180 bottom locked
TPJ814 "TP_SMD" TP_1.0_SMD 84.35,54.3 r180 bottom locked
TPJ817 "TP_SMD" TP_1.0_SMD 102.65,48.35 r180 bottom locked
TPJ818 "TP_SMD" TP_1.0_SMD 71.55,40.95 r180 bottom locked
TPJ820 "TP_SMD" TP_1.0_SMD 80.2,50.95 r180 bottom locked
TPJ900 "TP_SMD" TP_1.0_SMD 41.602,37.9 r90 bottom locked
TPJ901 "TP_SMD" TP_1.0_SMD 44.053,38.55 r90 bottom locked
TPJ902 "TP_SMD" TP_1.0_SMD 24.6,41.4 r180 bottom locked
TPJ905 "TP_SMD" TP_1.0_SMD 54.678,41.126 r90 bottom locked
TPJ908 "TP_SMD" TP_1.0_SMD 43.952,45.601 r90 bottom locked
TPJ909 "TP_SMD" TP_1.0_SMD 42.651,43.427 r90 bottom locked
TPJ910 "TP_SMD" TP_1.0_SMD 48.003,29.65 r90 bottom locked
TPJ911 "TP_SMD" TP_1.0_SMD 45.453,28.85 r90 bottom locked
TPJ912 "TP_SMD" TP_1.0_SMD 50.751,34.225 r90 bottom locked
TPJ913 "TP_SMD" TP_1.0_SMD 50.751,30.501 r90 bottom locked
TPJ950 "TP_SMD" TP_1.0_SMD 24.452,17.1 r90 bottom locked
TPJ953 "TP_SMD" TP_1.0_SMD 42.001,25.251 r90 bottom locked
TPJ954 "TP_SMD" TP_1.0_SMD 43.253,27.501 r90 bottom locked
TPJ955 "TP_SMD" TP_1.0_SMD 44.503,25.251 r90 bottom locked
TPJ956 "TP_SMD" TP_1.0_SMD 52.753,39.251 r90 bottom locked
TPJ957 "TP_SMD" TP_1.0_SMD 51.799,27.599 r180 bottom locked
TPJ958 "TP_SMD" TP_1.0_SMD 53.15,25.45 r180 bottom locked
TPJ959 "TP_SMD" TP_1.0_SMD 54.499,27.599 r90 bottom locked
TPJ960 "TP_SMD" TP_1.0_SMD 53.899,32.598 r90 bottom locked
TPJ961 "TP_SMD" TP_1.0_SMD 53.95,30.05 r180 bottom locked
U1 "EFM32PG23B310F512IM48-B" QFN48_M040_6.0X6.0_EP4.3X4.3_SI_EFM32PG23 85.6,32.8 r0 top
U101 "TS3A4751" QFN14_M040_2.0X2.0_TI_RUC#1 61.4,34.8 r90 top
U102 "Si7021-A20" DFN6_M100_3.0X3.0_EP_SI7021 111.45,50.05 r90 top
U600 "LP3982ILD-ADJ" WSON8_M050_3.0X2.5_EP_TI_NGM 14.45,54.95 r0 top
U603 "TLV70536" DSBGA4_M040_0.8X0.8_TI_YFP 44.35,29.45 r180 top
U606 "MCP6001T" SC70-5 48.5,26.8 r270 top
U622 "MCP6001T" SC70-5 57,32.35 r180 top
U700 "SIP32431" TDFN4_M050_1.6X1.2_EP_VISH 33.3,29.75 r90 top
U701 "LP3982ILD-ADJ" WSON8_M050_3.0X2.5_EP_TI_NGM 39.9,27.9 r270 top
U702 "TS3A4751" QFN14_M040_2.0X2.0_TI_RUC#1 42.7,33.675 r180 top
U703 "LTC6102CDD" DFN8_M050_3.0X3.0_EP_LT_DD 37.65,36.3 r180 top
U704 "AD8656" MSOP8_M065_W3.0 36.45,41 r0 top
U800 "74LVC4066" DHVQFN14_M050_2.5X3_EP_NXP 67.5,44.5 r270 top
U802 "74LVC4066" DHVQFN14_M050_2.5X3_EP_NXP 67.5,40 r270 top
U803 "74LVC2G125" DSBGA8_M050_0.9X1.9_TI_YZP 57.75,36.475 r0 top
U804 "74LVC2G125" DSBGA8_M050_0.9X1.9_TI_YZP 53.475,35.45 r180 top
U805 "TS3A4751" QFN14_M040_2.0X2.0_TI_RUC#2 61.375,37.97 r90 top
U806 "74LVC4066" DHVQFN14_M050_2.5X3_EP_NXP 67.5,35.5 r270 top
U808 "74LVC8T245" VQFN24_M050_3.5X5.5_EP_TI_RHL 60,43.95 r0 top
U809 "74LVC2G125" DSBGA8_M050_0.9X1.9_TI_YZP 53.5,38.675 r180 top
U810 "74LVC4066" DHVQFN14_M050_2.5X3_EP_NXP 67.5,31 r270 top
U812 "TS3A4751" QFN14_M040_2.0X2.0_TI_RUC#1 63.7,30.95 r90 top
U860 "74LVC1T45" X2-DFN1010-6_M035_DIODES 53.85,45 r180 top
U861 "74LVC1T45" X2-DFN1010-6_M035_DIODES 64.2,40.8 r90 top
U862 "74LVC1T45" X2-DFN1010-6_M035_DIODES 59.05,39.1 r90 top
U863 "74LVC1T45" X2-DFN1010-6_M035_DIODES 64.3,34.7 r90 top
U900 "EFM32GG12B410F1024GL120-A" BGA120_M050_7.0X7.0_EFM32GGR 48.5,41.5 r180 top
U901 "M24C02" TDFN8_M050_2.0X3.0_EP 53.75,47 r0 top
U902 "MX25R8035F" BGA8_M040_1.24X1.75_WLCSP 52.85,32.3 r0 top
U910 "ADC084S021" VSSOP10_M050_W3.0_TI_DGS 48.425,32.025 r0 top
U950 "TS3A4751" QFN14_M040_2.0X2.0_TI_RUC#1 55.125,41.9 r270 top
X1 "39_MHz" X_TAI_SAW_TZ3541C_2.0X1.6-4 80.85,30.275 r270 top
X2 "32.768_kHz" X_KDS_DST1610A_1610 81.275,35.95 r90 top
X900 "48_MHz" X_SSS_DSX211SH_2.05X1.65-4 47.6,46.65 r0 top

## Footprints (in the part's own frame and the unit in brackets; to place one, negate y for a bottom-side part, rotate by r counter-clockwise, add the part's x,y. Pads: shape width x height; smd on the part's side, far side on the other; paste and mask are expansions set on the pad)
BAT_HOLD_MPD_BK-912_CR2032 [mil] "MPD Battery Holder BK-912 (for CR2032)"
  rrect20% 110x200 smd: 1(-430,0) 1(430,0)
  round 157.48 smd paste-295.67 mask-82.68: 2(0,0)
  body extent -450,-394 450,394, height 171
BGA8_M040_1.24X1.75_WLCSP [mm] "BGA, 8 pin. U100"
  round 0.21 smd mask+0.05: A1(-0.35,0.4) A3(0.35,0.4) B2(0,0.2) C1(-0.35,0) C3(0.35,0) D2(0,-0.2) E1(-0.35,-0.4) E3(0.35,-0.4)
  body extent -0.63,-0.89 0.63,0.88, height 0.52
BGA120_M050_7.0X7.0_EFM32GGR [mm] "BGA, 120 Leads, Body 7.0x7.0mmx1,30mm, Pitch 0.50mm (191111)"
  round 0.2 smd mask+0.04: A1(-3,3) A2(-2.5,3) A3(-2,3) A4(-1.5,3) A5(-1,3) A6(-0.5,3) A7(0,3) A8(0.5,3) A9(1,3) A10(1.5,3) A11(2,3) A12(2.5,3) A13(3,3) B1(-3,2.5) B2(-2.5,2.5) B3(-2,2.5) B4(-1.5,2.5) B5(-1,2.5) B6(-0.5,2.5) B7(0,2.5) B8(0.5,2.5) B9(1,2.5) B10(1.5,2.5) B11(2,2.5) B12(2.5,2.5) B13(3,2.5) C1(-3,2) C2(-2.5,2) C3(-2,2) C4(-1.5,2) C5(-1,2) C6(-0.5,2) C7(0,2) C8(0.5,2) C9(1,2) C10(1.5,2) C11(2,2) C12(2.5,2) C13(3,2) D1(-3,1.5) D2(-2.5,1.5) D3(-2,1.5) D11(2,1.5) D12(2.5,1.5) D13(3,1.5) E1(-3,1) E2(-2.5,1) E3(-2,1) E11(2,1) E12(2.5,1) E13(3,1) F1(-3,0.5) F2(-2.5,0.5) F3(-2,0.5) F11(2,0.5) F12(2.5,0.5) F13(3,0.5) G1(-3,0) G2(-2.5,0) G3(-2,0) G11(2,0) G12(2.5,0) G13(3,0) H1(-3,-0.5) H2(-2.5,-0.5) H3(-2,-0.5) H11(2,-0.5) H12(2.5,-0.5) H13(3,-0.5) J1(-3,-1) J2(-2.5,-1) J3(-2,-1) J11(2,-1) J12(2.5,-1) J13(3,-1) K1(-3,-1.5) K2(-2.5,-1.5) K3(-2,-1.5) K11(2,-1.5) K12(2.5,-1.5) K13(3,-1.5) L1(-3,-2) L2(-2.5,-2) L3(-2,-2) L4(-1.5,-2) L5(-1,-2) L6(-0.5,-2) L7(0,-2) L8(0.5,-2) L9(1,-2) L10(1.5,-2) L11(2,-2) L12(2.5,-2) L13(3,-2) M1(-3,-2.5) M2(-2.5,-2.5) M3(-2,-2.5) M4(-1.5,-2.5) M5(-1,-2.5) M6(-0.5,-2.5) M7(0,-2.5) M8(0.5,-2.5) M9(1,-2.5) M10(1.5,-2.5) M11(2,-2.5) M12(2.5,-2.5) M13(3,-2.5) N1(-3,-3) N2(-2.5,-3) N3(-2,-3) N4(-1.5,-3) N5(-1,-3) N6(-0.5,-3) N7(0,-3) N8(0.5,-3) N9(1,-3) N10(1.5,-3) N11(2,-3) N12(2.5,-3) N13(3,-3)
  body extent -3.5,-3.5 3.5,3.5, height 1.3
C0201 [mm] "Capacitor, 9291, HiDens (170502)"
  rrect25% 0.36x0.32 smd paste-0.015: 1(-0.275,0) 2(0.275,0)
  Top Layer pour cut-out: -0.075,-0.2 -0.075,0.2 0.075,0.2 0.075,-0.2
  body extent -0.32,-0.13 0.32,0.13, height 0.3
C0402 [mm] "Chip Capacitor, 2-Leads, Body 1.0x0.5mm, IPC High Density (190308)"
  rrect20% 0.5x0.5 smd mask+0.051: 1(-0.5,0) 2(0.5,0)
  Top Layer pour cut-out: -0.225,-0.3 -0.225,0.3 0.225,0.3 0.225,-0.3
  body extent -0.5,-0.25 0.5,0.25, height 0.6
C0603 [mm] "Capacitor, 0603, HiDens (190130)"
  rrect25% 0.8x0.85 smd: 1(-0.7,0) 2(0.7,0)
  Top Layer pour cut-out: -0.275,-0.55 -0.275,0.55 0.275,0.55 0.275,-0.55
  body extent -0.88,-0.48 0.87,0.48, height 0.95
CK_DPDT_JS202011SCQN [mm] "Switch, C & K DPDT JS202011SCQN (190314)"
  rrect50% 1.2x2.5 smd: 1(-2.5,-2.75) 2(0,-2.75) 3(2.5,-2.75) 4(-2.5,2.75) 5(0,2.75) 6(2.5,2.75)
COIL_0402 [mm] "COIL_0402_L (3D from Wurth) (190308)"
  rrect20% 0.55x0.5 smd mask+0.051: 1(-0.525,0) 2(0.525,0)
  body extent -0.5,-0.25 0.5,0.25, height 0.5
COIL_1008 [mm] "Coil, HiDens (C) (190312)"
  rrect15% 0.93x2.12 smd: 1(-1.035,0) 2(1.035,0)
  body extent -1.35,-1.1 1.35,1.1, height 1
COIL_BOURNS_SDR0604 [mm] "Coil Bourns SDR0604 (210208)"
  rrect20% 1x1 smd paste-100: 1(-2,0) 2(2,0)
  Top Layer region: -3,-2.101 -3,2.1 -2.939,2.406 -2.766,2.666 -2.506,2.839 -2.2,2.9 -2.2,2.9 -1,2.9 -0.962,2.892 -0.929,2.871 -0.908,2.838 -0.9,2.8 -0.9,2.8 -0.9,-2.8 -0.908,-2.838 -0.929,-2.871 -0.962,-2.892 -1,-2.9 -1,-2.9 -2.2,-2.9 -2.6,-2.793 -2.892,-2.501 -3,-2.101
  Top Layer region: 3,2.101 3,-2.1 2.939,-2.406 2.766,-2.666 2.506,-2.839 2.2,-2.9 2.2,-2.9 1,-2.9 0.962,-2.892 0.929,-2.871 0.908,-2.838 0.9,-2.8 0.9,-2.8 0.9,2.8 0.908,2.838 0.929,2.871 0.962,2.892 1,2.9 1,2.9 2.2,2.9 2.6,2.793 2.892,2.501 3,2.101
  body extent -2.9,-2.9 2.9,2.9, height 4.81
COIL_WURTH_CBF_0603 [mm] "COIL_WURTH_CBF_0603 (= L0603_0.8_L) (181031)"
  rrect10% 0.67x0.88 smd: 1(-0.665,0) 2(0.665,0)
  body extent -0.87,-0.48 0.87,0.48, height 0.95
DFN6_M100_3.0X3.0_EP_SI7021 [mm] "(191031)"
  rrect20% 0.85x0.45 smd: 1(-1.45,1) 2(-1.45,0) 3(-1.45,-1) 4(1.45,-1) 5(1.45,0) 6(1.45,1)
  rrect20% 1.6x2.5 smd: 7(0,0)
  body extent -1.5,-1.5 1.5,1.5, height 1.22
DFN8_M050_3.0X3.0_EP_LT_DD [mm] "DFN 8 Lead, Pitch 0.5, 3.0x3.0x0.75 Exposed Pad, Linear Tech (171004)"
  rrect50% 0.7x0.25 smd paste-0.025 mask+0.07: 1(-1.4,0.75) 2(-1.4,0.25) 3(-1.4,-0.25) 4(-1.4,-0.75) 5(1.4,-0.75) 6(1.4,-0.25) 7(1.4,0.25) 8(1.4,0.75)
  rect 1x1.8 smd paste-1 mask+0: 9(0,0)
  Top Layer region: 0.825,1.2 -0.693,1.2 -0.825,1.095 -0.825,-1.2 0.825,-1.2
  body extent -1.56,-1.55 1.56,1.55, height 0.8
DFN2111-7_M050_1.2X2.1_NXP [mm] "DFN2111-7 NXP Pitch 035 1.2x2.1x0.5, NXP (190312)"
  rrect20% 0.53x0.19 smd mask+0.05: 1(-0.415,0.75) 2(-0.415,0.25) 3(-0.415,-0.25) 4(-0.415,-0.75) 5(0.415,-0.5) 6(0.415,0) 7(0.415,0.5)
  body extent -0.6,-1.05 0.6,1.05, height 0.51
DHVQFN14_M050_2.5X3_EP_NXP [mm] "DHVQFN, 14 Leads, 2.5x3.0x0.85, Pitch 0.50, Thermal Pad 1.0x1.5 (190314)"
  oval 0.3x0.7 smd: 1(-0.25,1.45) 7(-0.25,-1.45) 8(0.25,-1.45) 14(0.25,1.45)
  oval 0.7x0.3 smd: 2(-1.2,1) 3(-1.2,0.5) 4(-1.2,0) 5(-1.2,-0.5) 6(-1.2,-1) 9(1.2,-1) 10(1.2,-0.5) 11(1.2,0) 12(1.2,0.5) 13(1.2,1)
  rrect10% 1x1.5 smd: 17(0,0)
  body extent -1.25,-1.5 1.25,1.5, height 1.1
DSBGA4_M040_0.8X0.8_TI_YFP [mm] "DS-BGA, 4 Leads, Body 0.8x0.8 H:0.5, Pitch 0.40"
  round 0.23 smd mask+0.04: A1(-0.2,0.2) A2(0.2,0.2) B1(-0.2,-0.2) B2(0.2,-0.2)
  body extent -0.4,-0.4 0.4,0.4, height 0.51
DSBGA8_M050_0.9X1.9_TI_YZP [mm] "DS-BGA, 8 Leads, Body 0.9x1.9 H:0.5, Pitch 0.50"
  round 0.23 smd: A1(-0.25,0.75) A2(0.25,0.75) B1(-0.25,0.25) B2(0.25,0.25) C1(-0.25,-0.25) C2(0.25,-0.25) D1(-0.25,-0.75) D2(0.25,-0.75)
  body extent -0.45,-0.95 0.45,0.95, height 0.51
FCI_10137065_USB-C_RCPT [mm] "FCI AMPHENOL 10137065 USB-C Receptacle (Slot PinInPaste) (180404)"
  oval 1.3x2.6 hole 0.7 slot 2 at 90 deg: 25(-4.32,-3.05) 26(4.32,-3.05)
  oval 1.3x2.6 on Top Paste: 25(-4.32,-3.05) 26(4.32,-3.05)
  oval 1.2x2.3 hole 0.6 slot 1.9 at 90 deg: 27(-4.32,2) 28(4.32,2)
  oval 1.2x2.3 on Top Paste: 27(-4.32,2) 28(4.32,2)
  oval 1.347x1.1 hole 0.6 slot 1.247 at 0 deg: 27(-4.025,1.4) 28(4.025,1.4)
  oval 1.347x1.1 on Top Paste: 27(-4.025,1.4) 28(4.025,1.4)
  rrect20% 0.27x0.9 smd mask+0.076: A1(-2.625,2.7) A2(-2.125,2.7) A3(-1.625,2.7) A4(-1.125,2.7) A5(-0.625,2.7) A6(-0.125,2.7) A7(0.375,2.7) A8(0.875,2.7) A9(1.375,2.7) A10(1.875,2.7) A11(2.375,2.7) A12(2.875,2.7)
  rrect20% 0.27x0.8 smd mask+0.076: B1(2.625,1.1) B2(2.125,1.1) B3(1.625,1.1) B4(1.125,1.1) B5(0.625,1.1) B6(0.125,1.1) B7(-0.375,1.1) B8(-0.875,1.1) B9(-1.375,1.1) B10(-1.875,1.1) B11(-2.375,1.1) B12(-2.875,1.1)
  round 0 hole 0.6 unplated mask+0.102: M1(-3.6,0)
  round 0 hole 0.5 slot 0.85 at 0 deg unplated mask+0.102: M2(3.6,0)
  Top Layer keep-out region: -3.9,-4.85 3.9,-4.85 3.9,0.4 -3.9,0.4
  body extent -4.47,-5.3 4.47,2.85, height 3.14
HDR_M254-1X2 [mm] "Connector; Header; 2 Position (170508)"
  round 1.6 hole 1: 1(0,0) 2(2.54,0)
  body extent -1.07,-1.17 3.61,1.17, height 8.12
HDR_M254-1X16_NO_3D [mm] "No 3D model for this component (200325)"
  round 1.5 hole 0.9: 1(0,0) 2(2.54,0) 3(5.08,0) 4(7.62,0) 5(10.16,0) 6(12.7,0) 7(15.24,0) 8(17.78,0) 9(20.32,0) 10(22.86,0) 11(25.4,0) 12(27.94,0) 13(30.48,0) 14(33.02,0) 15(35.56,0) 16(38.1,0)
HDR_SULLINS_M127_PEG-2X10 [mil] "Sullins, GRPB102VQS (180319)"
  rrect50% 30x87 smd: 1(-25,-72.5) 2(-25,72.5) 3(25,-72.5) 4(25,72.5) 5(75,-72.5) 6(75,72.5) 7(125,-72.5) 8(125,72.5) 9(175,-72.5) 10(175,72.5) 11(225,-72.5) 12(225,72.5) 13(275,-72.5) 14(275,72.5) 15(325,-72.5) 16(325,72.5) 17(375,-72.5) 18(375,72.5) 19(425,-72.5) 20(425,72.5)
  round 0 hole 39.37 mask+3.94: M1(0,0) M2(400,0)
  body extent -50,-100 450,101, height 197
HOLE_3.0_5.0_PL [mm] "Hole 3.0 mm, Plated (171122)"
  round 5 hole 3: 1(0,0)
HOLE_3.0_NPL [mm] "HOLE_3.0_NPL (170815)"
  round 0 hole 3 unplated mask+0.2: 1(0,0)
  body extent -1.5,-1.5 1.5,1.5
LABEL_4CORNERS_19.0X6.0 [mm]
  silkscreen extent -9.5,-3 9.5,3
LABEL_P101_PIN_TABLE_SL [mm]
  silkscreen extent -2.4,-12.5 2.4,12.5
LCD_TRI-T_CE322-1002-01 [mm] "(210211)"
  round 1.4 hole 0.8: 1(-9,-12.7) 2(-7,-12.7) 3(-5,-12.7) 4(-3,-12.7) 5(-1,-12.7) 6(1,-12.7) 7(3,-12.7) 8(5,-12.7) 9(7,-12.7) 10(9,-12.7) 11(9,12.7) 12(7,12.7) 13(5,12.7) 14(3,12.7) 15(1,12.7) 16(-1,12.7) 17(-3,12.7) 18(-5,12.7) 19(-7,12.7) 20(-9,12.7)
  body extent -19.5,-12.7 19.5,12.7, height 5.35
LED_0402 [mm] "Chip Diode, 2-Leads, Body 1.00x0.50mm, IPC High Density (170127)"
  rrect10% 0.45x0.6 smd: 1(-0.45,0) 2(0.45,0)
  body extent -0.55,-0.33 0.55,0.33, height 0.25
LED_0402_CAT2 [mm] "(200921)"
  rrect10% 0.45x0.6 smd: 1(-0.45,0) 2(0.45,0)
  body extent -0.55,-0.33 0.55,0.33, height 0.25
LED_AVAGO_HSMF-C165-4 [mm] "LED (dual) Avago HSMF-C165 Grn+Red 1.6x0.8x0.5 (200226)"
  rrect20% 0.7x0.4 smd: 1(-0.65,-0.35) 2(-0.65,0.35) 3(0.65,0.35) 4(0.65,-0.35)
  body extent -0.8,-0.4 0.8,0.4, height 0.52
LOGO_EFM32_W18.0 [mm]
  silkscreen extent 12.4,0.08 18.08,2.31
LOGO_GECKO_H6.0 [mm] "Silicon Labs, Gecko logo"
  silkscreen extent 0.03,0.04 5.31,6.01
LOGO_SEGGER_10.0X5.0_SM [mm] "Logo, Segger 10.0x5.0, Top Solder + M19 + Top Overlay"
LOGO_SILABS_W14.0_SILK [mm] "LOGO_SILABS_W14.0 SILKSCREEN ONLY"
  silkscreen extent 0.03,0 13.99,6.83
LOGO_SILABS_W18.0 [mm]
  silkscreen extent 0.02,0.02 16.98,8.32
MSOP8_M065_W3.0 [mm] "MSOP, 8-Leads, Body 3.0x3.0mm, Pitch 0.65mm (170921)"
  rrect20% 0.889x0.42 smd mask+0.048: 1(-2.105,0.975) 2(-2.105,0.325) 3(-2.105,-0.325) 4(-2.105,-0.975) 5(2.106,-0.975) 6(2.106,-0.325) 7(2.106,0.325) 8(2.106,0.975)
  body extent -1.55,-1.55 1.55,1.55, height 1.11
POWERPAK_SC70-6 [mm] "POWERPAK SC70-6 HiDens (Vishay) (170926)"
  rrect10% 0.325x0.3 smd paste-0.025 mask+0.07: 1(-0.913,0.65) 2(-0.913,0) 3(-0.913,-0.65) 4(0.913,-0.65) 5(0.913,0) 6(0.913,0.65)
  rrect10% 0.95x0.613 smd paste-0.025 mask+0.07: 7(0,0.466) 8(0,-0.466)
  body extent -1.02,-1.02 1.02,1.05, height 0.8
PROTO_TH [mil] "Test Point, 1.0 mm (= TP_1.0_D62)"
  round 62 hole 39.37: 1(0,0)
QFN14_M040_2.0X2.0_TI_RUC#1 [mm] "QFN 14 Leads, Pitch 0.4 mm, 2.0 x 2.0 H: 0.37, TI: RUC (180613)"
  rrect20% 0.68x0.2 smd paste+0 mask+0.05: 1(-0.885,0.8) 2(-0.885,0.4) 3(-0.885,0) 4(-0.885,-0.4) 5(-0.885,-0.8) 8(0.885,-0.8) 9(0.885,-0.4) 10(0.885,0) 11(0.885,0.4) 12(0.885,0.8)
  rrect20% 0.2x0.68 smd paste+0 mask+0.05: 6(-0.2,-0.885) 7(0.2,-0.885) 13(0.2,0.885) 14(-0.2,0.885)
  body extent -1,-1 1,1, height 0.41
QFN14_M040_2.0X2.0_TI_RUC#2 [mm] "QFN 14 Leads, Pitch 0.4 mm, 2.0 x 2.0 H: 0.37, TI: RUC (180613)"
  rrect20% 0.68x0.2 smd: 1(-0.885,0.8) 2(-0.885,0.4) 3(-0.885,0) 4(-0.885,-0.4) 5(-0.885,-0.8) 8(0.885,-0.8) 9(0.885,-0.4) 10(0.885,0) 11(0.885,0.4) 12(0.885,0.8)
  rrect20% 0.2x0.68 smd: 6(-0.2,-0.885) 7(0.2,-0.885) 13(0.2,0.885) 14(-0.2,0.885)
  body extent -1,-1 1,1, height 0.41
QFN48_M040_6.0X6.0_EP4.3X4.3_SI_EFM32PG23 [mm] "QFN48, Pitch 0.4, 6.0x6.0 H0.9 (210208)"
  rrect5% 4.45x4.45 smd paste-100: 0(0,0)
  rrect20% 0.86x0.22 smd: 1(-2.935,2.2) 2(-2.935,1.8) 3(-2.935,1.4) 4(-2.935,1) 5(-2.935,0.6) 6(-2.935,0.2) 7(-2.935,-0.2) 8(-2.935,-0.6) 9(-2.935,-1) 10(-2.935,-1.4) 11(-2.935,-1.8) 12(-2.935,-2.2) 25(2.935,-2.2) 26(2.935,-1.8) 27(2.935,-1.4) 28(2.935,-1) 29(2.935,-0.6) 30(2.935,-0.2) 31(2.935,0.2) 32(2.935,0.6) 33(2.935,1) 34(2.935,1.4) 35(2.935,1.8) 36(2.935,2.2)
  rrect20% 0.22x0.86 smd: 13(-2.2,-2.935) 14(-1.8,-2.935) 15(-1.4,-2.935) 16(-1,-2.935) 17(-0.6,-2.935) 18(-0.2,-2.935) 19(0.2,-2.935) 20(0.6,-2.935) 21(1,-2.935) 22(1.4,-2.935) 23(1.8,-2.935) 24(2.2,-2.935) 37(2.2,2.935) 38(1.8,2.935) 39(1.4,2.935) 40(1,2.935) 41(0.6,2.935) 42(0.2,2.935) 43(-0.2,2.935) 44(-0.6,2.935) 45(-1,2.935) 46(-1.4,2.935) 47(-1.8,2.935) 48(-2.2,2.935)
  body extent -3.05,-3.05 3.05,3.05, height 0.91
R0201 [mm] "Resistor (Chip2PinSM127P600-8N) (170921)"
  rrect25% 0.34x0.32 smd: 1(-0.3,0) 2(0.3,0)
  Top Layer pour cut-out: -0.1,-0.2 -0.1,0.2 0.1,0.2 0.1,-0.2
  body extent -0.32,-0.13 0.32,0.13, height 0.3
R0402 [mm] "Chip Resistor, 2-Leads, Body 1.0x0.5mm, HiDens (190308)"
  rrect20% 0.6x0.6 smd mask+0.051: 1(-0.45,0) 2(0.45,0)
  Top Layer pour cut-out: -0.125,-0.3 -0.125,0.3 0.125,0.3 0.125,-0.3
  body extent -0.5,-0.25 0.5,0.25, height 0.6
R0603 [mm] "Chip Resistor, 0603, HiDens (190130)"
  rrect25% 0.85x0.9 smd: 1(-0.7,0) 2(0.7,0)
  Top Layer pour cut-out: -0.25,-0.575 -0.25,0.575 0.25,0.575 0.25,-0.575
  body extent -0.88,-0.48 0.87,0.48, height 0.95
R1206 [mm] "Resistor, 1206, HiDens (191114)"
  rrect25% 0.85x1.65 smd paste-0.04 mask+0.07: 1(-1.425,0) 2(1.425,0)
  body extent -1.6,-0.8 1.6,0.8, height 1
RES_MNR04-8 [mm] "Resistor Array, ROHM MNR04 8-Pin 2.0x1.0x0.35 (!80615)"
  rrect20% 0.4x0.5 smd: 1(-0.75,-0.45) 4(0.75,-0.45) 5(0.75,0.45) 8(-0.75,0.45)
  rrect20% 0.3x0.5 smd: 2(-0.25,-0.45) 3(0.25,-0.45) 6(0.25,0.45) 7(-0.25,0.45)
  body extent -1,-0.4 1,0.4, height 0.5
SC70-5 [mm] "SC70-5 = SOT353, HiDens (170511)"
  rrect25% 0.6x0.4 smd paste-0.03 mask+0.05: 1(-0.95,0.65) 2(-0.95,0) 3(-0.95,-0.65) 4(0.95,-0.65) 5(0.95,0.65)
  body extent -1.12,-0.97 1.16,1.03, height 0.95
SC70_123 [mm] "SC70 = SOT323_123, HiDens (170509)"
  rrect25% 0.75x0.4 smd: 1(-1,0.65) 2(-1,-0.65) 3(1,0)
  body extent -1.1,-1 1.1,1, height 0.9
SOT23_123 [mm] "SOT23, 3-Leads, Body 2.95x2.80mm, Pitch 0.95mm, HiDens (171129)"
  rrect50% 0.9x0.6 smd: 1(-1.2,0.95) 2(-1.2,-0.95) 3(1.2,0)
  body extent -1.32,-1.5 1.32,1.5, height 1.08
SOT563 [mm] "SOT563 (_M050_W1.2_), 6-Leads, Body 1.60x1.20, Pitch 0.5, HiDens (170926)"
  rrect25% 0.6x0.3 smd: 1(-0.65,0.5) 2(-0.65,0) 3(-0.65,-0.5) 4(0.65,-0.5) 5(0.65,0) 6(0.65,0.5)
  body extent -0.65,-0.85 0.65,0.85, height 0.6
SOT563_DIODES [mm] "SOT563 (_M050_W1.2_), 6-Leads, Body 1.60x1.20, Pitch 0.5, HiDens (170926)"
  rrect25% 0.5x0.375 smd: 1(-0.85,0.5) 2(-0.85,0) 3(-0.85,-0.5) 4(0.85,-0.5) 5(0.85,0) 6(0.85,0.5)
  body extent -0.66,-0.85 0.65,0.85, height 0.6
SW_CK_PTS810_SJM_250 [mm] "Switch C&K PTS810_SJM_250 (grey button) (180319)"
  rrect20% 1.05x0.65 smd: 1(-2.075,1.075) 2(2.075,1.075) 3(-2.075,-1.075) 4(2.075,-1.075)
  body extent -2.29,-1.6 2.29,1.6, height 2.5
TAB_V-CUT_L7.0_W2.4 [mm] "TAB V_CUT, Length 7.0, Width 2.4"
TDFN4_M050_1.6X1.2_EP_VISH [mm] "TDFN, 4-Leads, Body 1.60x1.20mm, IPC HiDens (180111)"
  rrect10% 0.55x0.3 smd: 1(-0.725,0.25) 2(-0.725,-0.25) 3(0.725,-0.25) 4(0.725,0.25)
  rrect10% 0.5x0.86 smd paste-0.05: 5(0,0)
  body extent -0.8,-0.6 0.8,0.6, height 0.61
TDFN8_M050_2.0X3.0_EP [mm] "TDFN8_M050_2.0x3.0_EP (170921)"
  rrect20% 0.75x0.3 smd: 1(-1.45,0.75) 2(-1.45,0.25) 3(-1.45,-0.25) 4(-1.45,-0.75) 5(1.45,-0.75) 6(1.45,-0.25) 7(1.45,0.25) 8(1.45,0.75)
  rrect10% 1.5x1.4 smd: 9(0,0)
  body extent -1.5,-1 1.5,1, height 1.01
TP_1.0_SMD [mm] "Test Point, 1.0 mm, SMD (170509)"
  round 1 smd paste-0.501: 1(0,0)
  body extent -0.5,-0.5 0.5,0.5, height 0.04
VQFN24_M050_3.5X5.5_EP_TI_RHL [mm] "VQFN 24 Leads, Pitch 0.50 3.5x5.0x0.9, TI: RHL (171011)"
  rrect20% 0.28x0.99 smd: 1(-0.75,2.795) 12(-0.75,-2.795) 13(0.75,-2.795) 24(0.75,2.795)
  rrect20% 0.99x0.28 smd: 2(-1.795,2.25) 3(-1.795,1.75) 4(-1.795,1.25) 5(-1.795,0.75) 6(-1.795,0.25) 7(-1.795,-0.25) 8(-1.795,-0.75) 9(-1.795,-1.25) 10(-1.795,-1.75) 11(-1.795,-2.25) 14(1.795,-2.25) 15(1.795,-1.75) 16(1.795,-1.25) 17(1.795,-0.75) 18(1.795,-0.25) 19(1.795,0.25) 20(1.795,0.75) 21(1.795,1.25) 22(1.795,1.75) 23(1.795,2.25)
  rrect5% 2.05x4.05 smd: 25(0,0)
  Top Layer region: -0.39,3.26 -0.39,2 0.39,2 0.39,3.26 0.388,3.272 0.381,3.281 0.372,3.288 0.36,3.29 0.36,3.29 0.14,3.29 0.129,3.288 0.119,3.281 0.112,3.272 0.11,3.26 0.11,3.26 0.11,2.32 0.108,2.312 0.104,2.306 0.098,2.301 0.09,2.3 0.09,2.3 -0.09,2.3 -0.1,2.303 -0.107,2.31 -0.11,2.32 -0.11,2.32 -0.11,3.26 -0.112,3.272 -0.119,3.281 -0.129,3.288 -0.14,3.29 -0.14,3.29 -0.36,3.29 -0.372,3.288 -0.381,3.281 -0.388,3.271 -0.39,3.26
  Top Layer region: 0.39,-3.26 0.39,-2 -0.39,-2 -0.39,-3.26 -0.388,-3.272 -0.381,-3.281 -0.372,-3.288 -0.36,-3.29 -0.36,-3.29 -0.14,-3.29 -0.129,-3.288 -0.119,-3.281 -0.112,-3.272 -0.11,-3.26 -0.11,-3.26 -0.11,-2.32 -0.108,-2.312 -0.104,-2.306 -0.098,-2.301 -0.09,-2.3 -0.09,-2.3 0.09,-2.3 0.1,-2.303 0.107,-2.31 0.11,-2.32 0.11,-2.32 0.11,-3.26 0.112,-3.272 0.119,-3.281 0.129,-3.288 0.14,-3.29 0.14,-3.29 0.36,-3.29 0.372,-3.288 0.381,-3.281 0.388,-3.271 0.39,-3.26
  body extent -1.75,-2.75 1.75,2.75, height 1
VSSOP10_M050_W3.0_TI_DGS [mm] "VSSOP, 10-Leads, 3.0x3.0x(max1.1), Pitch 0.50mm, (TI: DGS) (190816)"
  rrect20% 1.45x0.3 smd: 1(-2.2,1) 2(-2.2,0.5) 3(-2.2,0) 4(-2.2,-0.5) 5(-2.2,-1) 6(2.2,-1) 7(2.2,-0.5) 8(2.2,0) 9(2.2,0.5) 10(2.2,1)
  body extent -1.5,-1.5 1.5,1.5, height 1.1
WCON_1125B-1210_HOR_PEG-2X10 [mm] "WCON 2x10 header (201021)"
  rrect50% 1.27x3.175 smd: 1(-1.27,4.24) 2(-1.27,8.43) 3(1.27,4.24) 4(1.27,8.43) 5(3.81,4.24) 6(3.81,8.43) 7(6.35,4.24) 8(6.35,8.43) 9(8.89,4.24) 10(8.89,8.43) 11(11.43,4.24) 12(11.43,8.43) 13(13.97,4.24) 14(13.97,8.43) 15(16.51,4.24) 16(16.51,8.43) 17(19.05,4.24) 18(19.05,8.43) 19(21.59,4.24) 20(21.59,8.43)
  round 0 hole 1.9 unplated paste+0.91 mask+0.1: M1(0,0) M2(20.32,0)
  body extent -2.54,-7.11 22.86,9.15, height 6.1
WCON_3132_HDR_M127_SMD-2X10 [mm] "WCON_3132_HDR_M127_SMD-2X10 (210215)"
  rrect50% 0.74x2.4 smd: 1(-5.715,-1.95) 2(-5.715,1.95) 3(-4.445,-1.95) 4(-4.445,1.95) 5(-3.175,-1.95) 6(-3.175,1.95) 7(-1.905,-1.95) 8(-1.905,1.95) 9(-0.635,-1.95) 10(-0.635,1.95) 11(0.635,-1.95) 12(0.635,1.95) 13(1.905,-1.95) 14(1.905,1.95) 15(3.175,-1.95) 16(3.175,1.95) 17(4.445,-1.95) 18(4.445,1.95) 19(5.715,-1.95) 20(5.715,1.95)
  body extent -6.35,-4.53 6.35,2.84, height 6.58
WELLSHOW_C02AN31_SMA_TH [mm] "Wellshow C02AN31P00101 SMA (210208)"
  round 2.54 hole 1.5: 1(0,0) 2(-2.54,-2.54) 3(2.54,-2.54) 4(2.54,2.54) 5(-2.54,2.54)
  body extent -3.2,-3.2 3.2,3.2, height 9.5
WSON8_M050_3.0X2.5_EP_TI_NGM [mm] "WSON8, Pitch 0.5, 3.0x2.5x0.8 EP TI: NGM (181205)"
  rrect20% 0.5x0.25 smd mask+0.051: 1(-1.15,0.75) 2(-1.15,0.25) 3(-1.15,-0.25) 4(-1.15,-0.75) 5(1.15,-0.75) 6(1.15,-0.25) 7(1.15,0.25) 8(1.15,0.75)
  rrect10% 1.2x1.5 smd mask+0.051: 9(0,0)
  body extent -1.5,-1.25 1.5,1.25, height 0.8
X2-DFN1006-2 [mm] "Diodes case X2-DFN1006-2 part DESD5V0S1BLD (201012)"
  rrect20% 0.4x0.7 smd mask+0.04: 1(-0.35,0) 2(0.35,0)
  body extent -0.5,-0.3 0.5,0.3, height 0.41
X2-DFN1010-6_M035_DIODES [mm] "X2-DFN1010-6 Pitch 0.35 1.0x1.0x0.4, Diodes Inc (181025)"
  rrect20% 0.55x0.2 smd mask+0.04: 1(-0.35,0.35) 2(-0.35,0) 3(-0.35,-0.35) 4(0.35,-0.35) 5(0.35,0) 6(0.35,0.35)
  body extent -0.5,-0.5 0.5,0.5, height 0.41
X2-DFN2015-3_DIODES [mm] "X2-DFN2015-3 DIODES (181204)"
  rrect10% 0.5x0.31 smd mask+0.07: 1(-0.9,0.5) 2(-0.9,-0.5)
  rrect10% 0.75x0.31 smd mask+0.07: 3(0.775,0)
  Top Layer region: 0.5,0.55 0.5,-0.55 0.487,-0.6 0.45,-0.637 0.4,-0.65 0.4,-0.65 -0.4,-0.65 -0.45,-0.637 -0.487,-0.6 -0.5,-0.55 -0.5,-0.55 -0.5,0.55 -0.487,0.6 -0.45,0.637 -0.4,0.65 -0.4,0.65 0.4,0.65 0.45,0.637 0.487,0.6 0.5,0.55
  body extent -1.04,-0.79 1.04,0.79, height 0.4
X_KDS_DST1610A_1610 [mm] "Crystal KDS DST1610A (2 pin) (190827)"
  rrect25% 0.4x0.8 smd mask+0.051: 1(-0.5,0) 2(0.5,0)
  body extent -0.8,-0.5 0.8,0.5, height 0.45
X_SSS_DSX211SH_2.05X1.65-4 [mm] "X_SSS_DSX211SH_2.05X1.65-4"
  rrect20% 0.9x0.8 smd: 1(-0.7,-0.55) 2(0.7,-0.55) 3(0.7,0.55) 4(-0.7,0.55)
  body extent -1.07,-0.87 1.07,0.87, height 0.51
X_TAI_SAW_TZ3541C_2.0X1.6-4 [mm] "(210211)"
  rrect20% 0.95x0.85 smd mask+0.051: 1(-0.725,-0.575) 2(0.725,-0.575) 3(0.725,0.575) 4(-0.725,0.575)
  body extent -1,-0.8 1,0.8, height 0.51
